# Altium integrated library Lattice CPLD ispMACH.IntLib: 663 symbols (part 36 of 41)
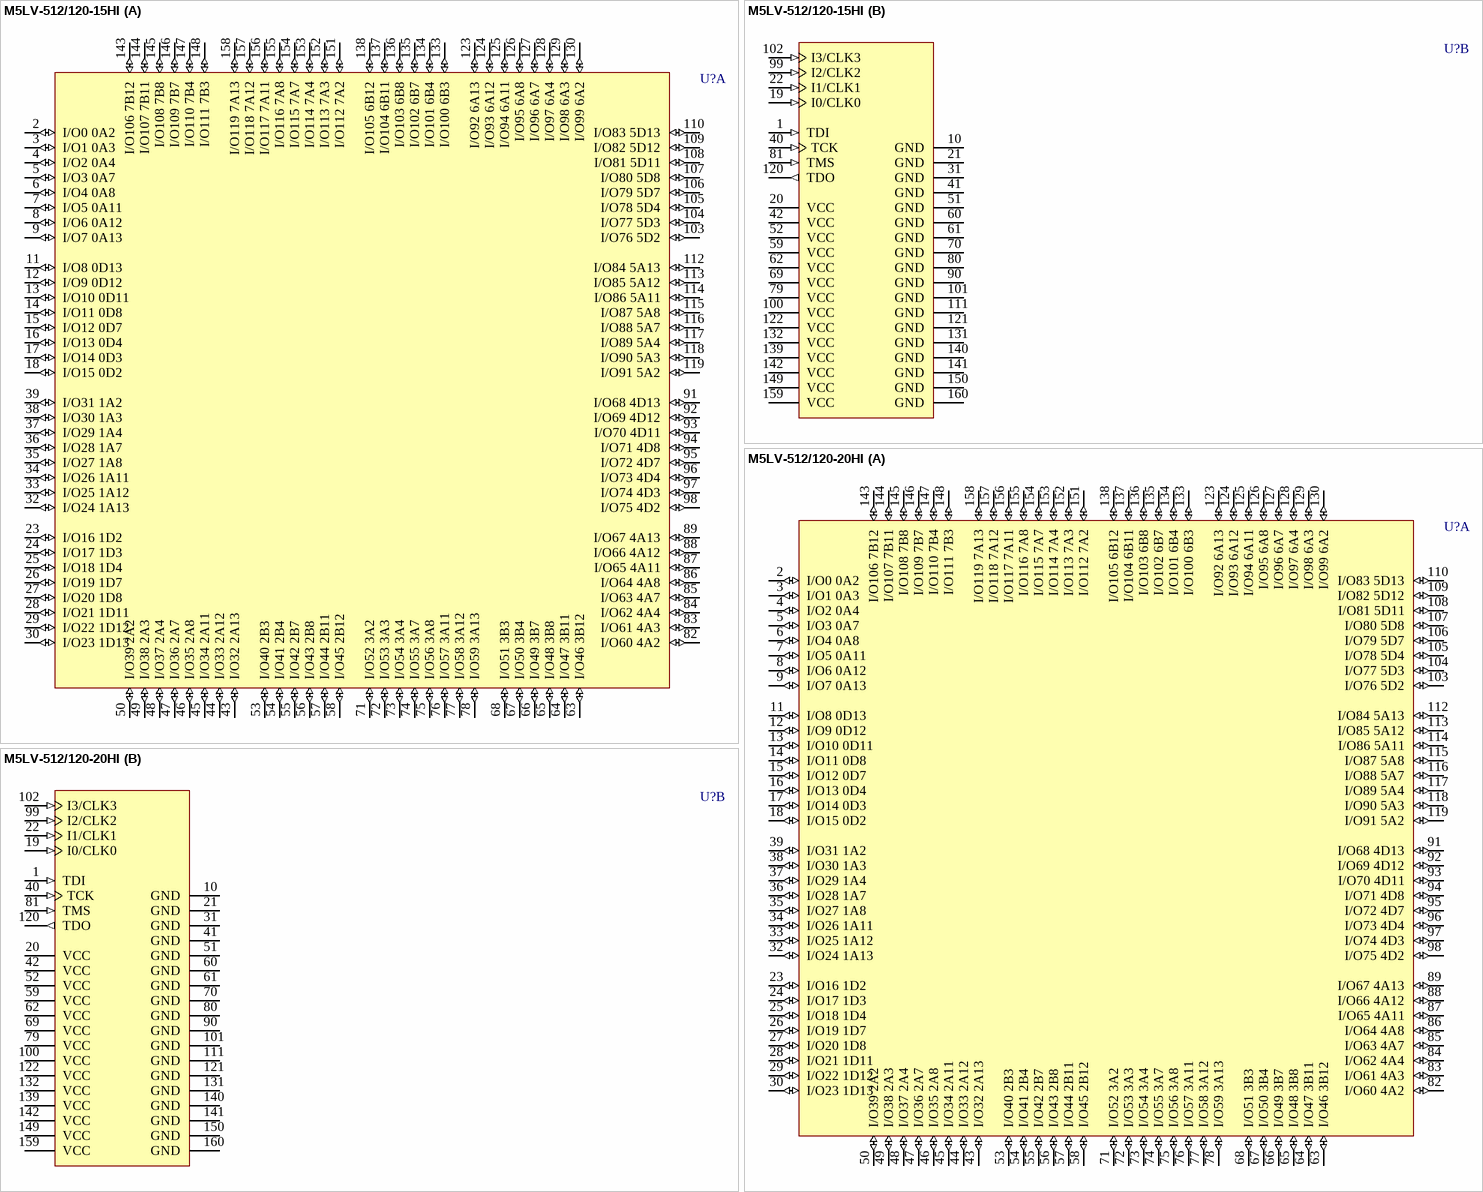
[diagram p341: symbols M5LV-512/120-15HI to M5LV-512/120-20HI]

## M5LV-512/120-15HI
designator U?
High-Density and High-I/O Complex PLD
footprint MQFP160_N (QFP, 160-Leads, Body 27.7 x 27.7mm, Pitch 0.65mm, IPC Medium Density)
footprint MQFP160_L (QFP, 160-Leads, Body 27.7 x 27.7mm, Pitch 0.65mm, IPC High Density)
footprint MQFP160_M (QFP, 160-Leads, Body 27.7 x 27.7mm, Pitch 0.65mm, IPC Low Density)
3D model M5LV-MQFP160 (160-Pin Quad Flat Pack 0.65 mm Pitch)
part A pins: 2 I/O0 0A2 (io), 3 I/O1 0A3 (io), 4 I/O2 0A4 (io), 5 I/O3 0A7 (io), 6 I/O4 0A8 (io), 7 I/O5 0A11 (io), 8 I/O6 0A12 (io), 9 I/O7 0A13 (io), 11 I/O8 0D13 (io), 12 I/O9 0D12 (io), 13 I/O10 0D11 (io), 14 I/O11 0D8 (io), 15 I/O12 0D7 (io), 16 I/O13 0D4 (io), 17 I/O14 0D3 (io), 18 I/O15 0D2 (io), 23 I/O16 1D2 (io), 24 I/O17 1D3 (io), 25 I/O18 1D4 (io), 26 I/O19 1D7 (io), 27 I/O20 1D8 (io), 28 I/O21 1D11 (io), 29 I/O22 1D12 (io), 30 I/O23 1D13 (io), 32 I/O24 1A13 (io), 33 I/O25 1A12 (io), 34 I/O26 1A11 (io), 35 I/O27 1A8 (io), 36 I/O28 1A7 (io), 37 I/O29 1A4 (io), 38 I/O30 1A3 (io), 39 I/O31 1A2 (io), 43 I/O32 2A13 (io), 44 I/O33 2A12 (io), 45 I/O34 2A11 (io), 46 I/O35 2A8 (io), 47 I/O36 2A7 (io), 48 I/O37 2A4 (io), 49 I/O38 2A3 (io), 50 I/O39 2A2 (io), 53 I/O40 2B3 (io), 54 I/O41 2B4 (io), 55 I/O42 2B7 (io), 56 I/O43 2B8 (io), 57 I/O44 2B11 (io), 58 I/O45 2B12 (io), 63 I/O46 3B12 (io), 64 I/O47 3B11 (io), 65 I/O48 3B8 (io), 66 I/O49 3B7 (io), 67 I/O50 3B4 (io), 68 I/O51 3B3 (io), 71 I/O52 3A2 (io), 72 I/O53 3A3 (io), 73 I/O54 3A4 (io), 74 I/O55 3A7 (io), 75 I/O56 3A8 (io), 76 I/O57 3A11 (io), 77 I/O58 3A12 (io), 78 I/O59 3A13 (io), 82 I/O60 4A2 (io), 83 I/O61 4A3 (io), 84 I/O62 4A4 (io), 85 I/O63 4A7 (io), 86 I/O64 4A8 (io), 87 I/O65 4A11 (io), 88 I/O66 4A12 (io), 89 I/O67 4A13 (io), 91 I/O68 4D13 (io), 92 I/O69 4D12 (io), 93 I/O70 4D11 (io), 94 I/O71 4D8 (io), 95 I/O72 4D7 (io), 96 I/O73 4D4 (io), 97 I/O74 4D3 (io), 98 I/O75 4D2 (io), 103 I/O76 5D2 (io), 104 I/O77 5D3 (io), 105 I/O78 5D4 (io), 106 I/O79 5D7 (io), 107 I/O80 5D8 (io), 108 I/O81 5D11 (io), 109 I/O82 5D12 (io), 110 I/O83 5D13 (io), 112 I/O84 5A13 (io), 113 I/O85 5A12 (io), 114 I/O86 5A11 (io), 115 I/O87 5A8 (io), 116 I/O88 5A7 (io), 117 I/O89 5A4 (io), 118 I/O90 5A3 (io), 119 I/O91 5A2 (io), 123 I/O92 6A13 (io), 124 I/O93 6A12 (io), 125 I/O94 6A11 (io), 126 I/O95 6A8 (io), 127 I/O96 6A7 (io), 128 I/O97 6A4 (io), 129 I/O98 6A3 (io), 130 I/O99 6A2 (io), 133 I/O100 6B3 (io), 134 I/O101 6B4 (io), 135 I/O102 6B7 (io), 136 I/O103 6B8 (io), 137 I/O104 6B11 (io), 138 I/O105 6B12 (io), 143 I/O106 7B12 (io), 144 I/O107 7B11 (io), 145 I/O108 7B8 (io), 146 I/O109 7B7 (io), 147 I/O110 7B4 (io), 148 I/O111 7B3 (io), 151 I/O112 7A2 (io), 152 I/O113 7A3 (io), 153 I/O114 7A4 (io), 154 I/O115 7A7 (io), 155 I/O116 7A8 (io), 156 I/O117 7A11 (io), 157 I/O118 7A12 (io), 158 I/O119 7A13 (io)
part B pins: 1 TDI (in), 10 GND (power), 19 I0/CLK0 (in), 20 VCC (power), 21 GND (power), 22 I1/CLK1 (in), 31 GND (power), 40 TCK (in), 41 GND (power), 42 VCC (power), 51 GND (power), 52 VCC (power), 59 VCC (power), 60 GND (power), 61 GND (power), 62 VCC (power), 69 VCC (power), 70 GND (power), 79 VCC (power), 80 GND (power), 81 TMS (in), 90 GND (power), 99 I2/CLK2 (in), 100 VCC (power), 101 GND (power), 102 I3/CLK3 (in), 111 GND (power), 120 TDO (out), 121 GND (power), 122 VCC (power), 131 GND (power), 132 VCC (power), 139 VCC (power), 140 GND (power), 141 GND (power), 142 VCC (power), 149 VCC (power), 150 GND (power), 159 VCC (power), 160 GND (power)

## M5LV-512/120-20HI
designator U?
High-Density and High-I/O Complex PLD
footprint MQFP160_N (QFP, 160-Leads, Body 27.7 x 27.7mm, Pitch 0.65mm, IPC Medium Density)
footprint MQFP160_L (QFP, 160-Leads, Body 27.7 x 27.7mm, Pitch 0.65mm, IPC High Density)
footprint MQFP160_M (QFP, 160-Leads, Body 27.7 x 27.7mm, Pitch 0.65mm, IPC Low Density)
3D model M5LV-MQFP160 (160-Pin Quad Flat Pack 0.65 mm Pitch)
part A pins: 2 I/O0 0A2 (io), 3 I/O1 0A3 (io), 4 I/O2 0A4 (io), 5 I/O3 0A7 (io), 6 I/O4 0A8 (io), 7 I/O5 0A11 (io), 8 I/O6 0A12 (io), 9 I/O7 0A13 (io), 11 I/O8 0D13 (io), 12 I/O9 0D12 (io), 13 I/O10 0D11 (io), 14 I/O11 0D8 (io), 15 I/O12 0D7 (io), 16 I/O13 0D4 (io), 17 I/O14 0D3 (io), 18 I/O15 0D2 (io), 23 I/O16 1D2 (io), 24 I/O17 1D3 (io), 25 I/O18 1D4 (io), 26 I/O19 1D7 (io), 27 I/O20 1D8 (io), 28 I/O21 1D11 (io), 29 I/O22 1D12 (io), 30 I/O23 1D13 (io), 32 I/O24 1A13 (io), 33 I/O25 1A12 (io), 34 I/O26 1A11 (io), 35 I/O27 1A8 (io), 36 I/O28 1A7 (io), 37 I/O29 1A4 (io), 38 I/O30 1A3 (io), 39 I/O31 1A2 (io), 43 I/O32 2A13 (io), 44 I/O33 2A12 (io), 45 I/O34 2A11 (io), 46 I/O35 2A8 (io), 47 I/O36 2A7 (io), 48 I/O37 2A4 (io), 49 I/O38 2A3 (io), 50 I/O39 2A2 (io), 53 I/O40 2B3 (io), 54 I/O41 2B4 (io), 55 I/O42 2B7 (io), 56 I/O43 2B8 (io), 57 I/O44 2B11 (io), 58 I/O45 2B12 (io), 63 I/O46 3B12 (io), 64 I/O47 3B11 (io), 65 I/O48 3B8 (io), 66 I/O49 3B7 (io), 67 I/O50 3B4 (io), 68 I/O51 3B3 (io), 71 I/O52 3A2 (io), 72 I/O53 3A3 (io), 73 I/O54 3A4 (io), 74 I/O55 3A7 (io), 75 I/O56 3A8 (io), 76 I/O57 3A11 (io), 77 I/O58 3A12 (io), 78 I/O59 3A13 (io), 82 I/O60 4A2 (io), 83 I/O61 4A3 (io), 84 I/O62 4A4 (io), 85 I/O63 4A7 (io), 86 I/O64 4A8 (io), 87 I/O65 4A11 (io), 88 I/O66 4A12 (io), 89 I/O67 4A13 (io), 91 I/O68 4D13 (io), 92 I/O69 4D12 (io), 93 I/O70 4D11 (io), 94 I/O71 4D8 (io), 95 I/O72 4D7 (io), 96 I/O73 4D4 (io), 97 I/O74 4D3 (io), 98 I/O75 4D2 (io), 103 I/O76 5D2 (io), 104 I/O77 5D3 (io), 105 I/O78 5D4 (io), 106 I/O79 5D7 (io), 107 I/O80 5D8 (io), 108 I/O81 5D11 (io), 109 I/O82 5D12 (io), 110 I/O83 5D13 (io), 112 I/O84 5A13 (io), 113 I/O85 5A12 (io), 114 I/O86 5A11 (io), 115 I/O87 5A8 (io), 116 I/O88 5A7 (io), 117 I/O89 5A4 (io), 118 I/O90 5A3 (io), 119 I/O91 5A2 (io), 123 I/O92 6A13 (io), 124 I/O93 6A12 (io), 125 I/O94 6A11 (io), 126 I/O95 6A8 (io), 127 I/O96 6A7 (io), 128 I/O97 6A4 (io), 129 I/O98 6A3 (io), 130 I/O99 6A2 (io), 133 I/O100 6B3 (io), 134 I/O101 6B4 (io), 135 I/O102 6B7 (io), 136 I/O103 6B8 (io), 137 I/O104 6B11 (io), 138 I/O105 6B12 (io), 143 I/O106 7B12 (io), 144 I/O107 7B11 (io), 145 I/O108 7B8 (io), 146 I/O109 7B7 (io), 147 I/O110 7B4 (io), 148 I/O111 7B3 (io), 151 I/O112 7A2 (io), 152 I/O113 7A3 (io), 153 I/O114 7A4 (io), 154 I/O115 7A7 (io), 155 I/O116 7A8 (io), 156 I/O117 7A11 (io), 157 I/O118 7A12 (io), 158 I/O119 7A13 (io)
part B pins: 1 TDI (in), 10 GND (power), 19 I0/CLK0 (in), 20 VCC (power), 21 GND (power), 22 I1/CLK1 (in), 31 GND (power), 40 TCK (in), 41 GND (power), 42 VCC (power), 51 GND (power), 52 VCC (power), 59 VCC (power), 60 GND (power), 61 GND (power), 62 VCC (power), 69 VCC (power), 70 GND (power), 79 VCC (power), 80 GND (power), 81 TMS (in), 90 GND (power), 99 I2/CLK2 (in), 100 VCC (power), 101 GND (power), 102 I3/CLK3 (in), 111 GND (power), 120 TDO (out), 121 GND (power), 122 VCC (power), 131 GND (power), 132 VCC (power), 139 VCC (power), 140 GND (power), 141 GND (power), 142 VCC (power), 149 VCC (power), 150 GND (power), 159 VCC (power), 160 GND (power)

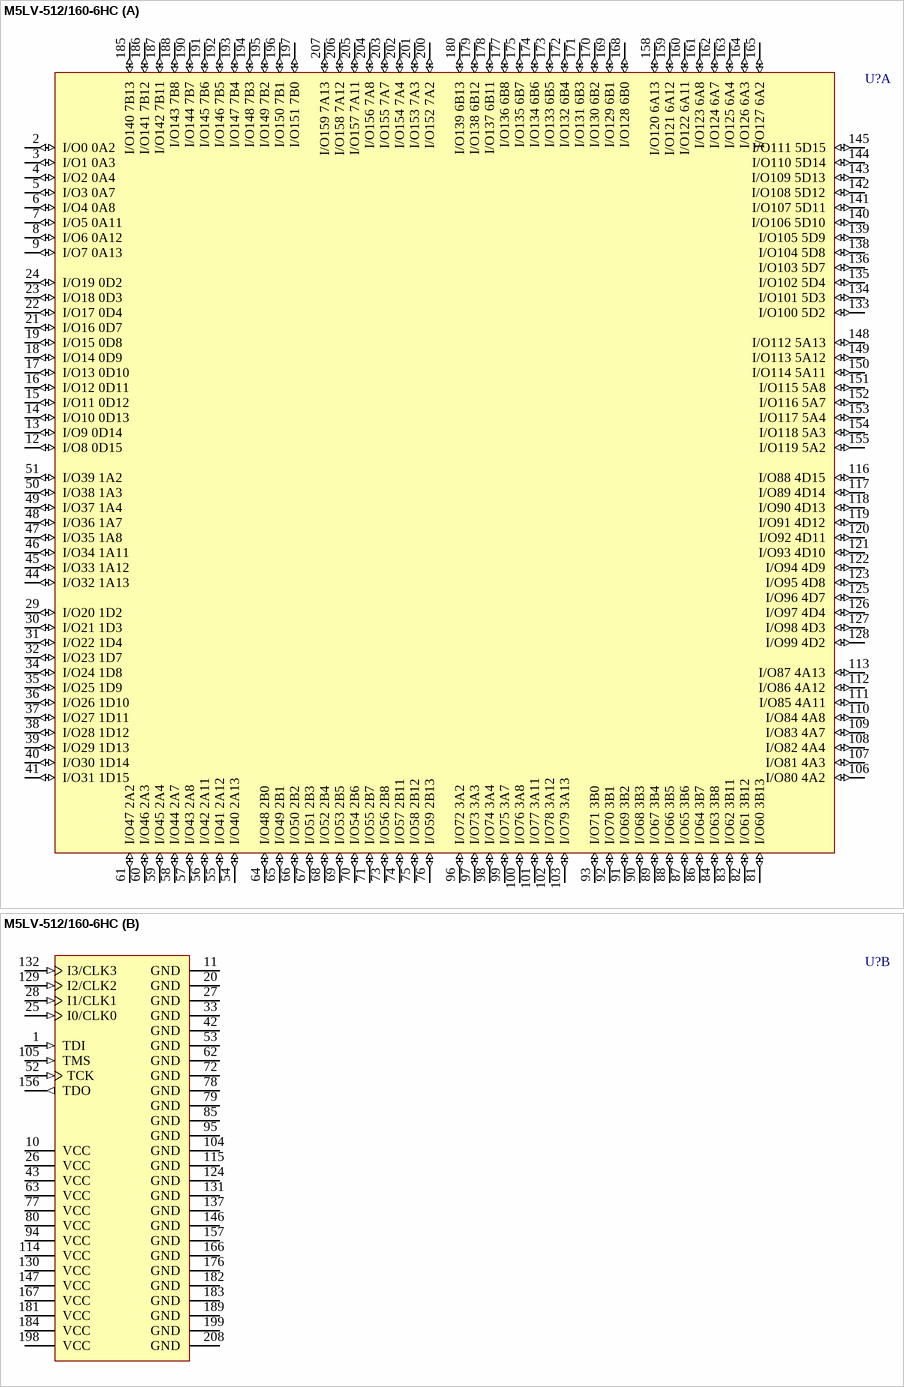
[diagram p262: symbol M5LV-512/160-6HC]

## M5LV-512/160-6HC
designator U?
High-Density and High-I/O Complex PLD
footprint MQFP208_N (Shrink QFP, 208-Leads, Body 27.7x27.7mm, Pitch 0.5mm, IPC Medium Density)
footprint MQFP208_L (Shrink QFP, 208-Leads, Body 27.7x27.7mm, Pitch 0.5mm, IPC High Density)
footprint MQFP208_M (Shrink QFP, 208-Leads, Body 27.7x27.7mm, Pitch 0.5mm, IPC Low Density)
3D model M5LV-MQFP208 (208-Pin Shrink Quad Flat Pack 0.5 mm Pitch)
part A pins: 2 I/O0 0A2 (io), 3 I/O1 0A3 (io), 4 I/O2 0A4 (io), 5 I/O3 0A7 (io), 6 I/O4 0A8 (io), 7 I/O5 0A11 (io), 8 I/O6 0A12 (io), 9 I/O7 0A13 (io), 12 I/O8 0D15 (io), 13 I/O9 0D14 (io), 14 I/O10 0D13 (io), 15 I/O11 0D12 (io), 16 I/O12 0D11 (io), 17 I/O13 0D10 (io), 18 I/O14 0D9 (io), 19 I/O15 0D8 (io), 21 I/O16 0D7 (io), 22 I/O17 0D4 (io), 23 I/O18 0D3 (io), 24 I/O19 0D2 (io), 29 I/O20 1D2 (io), 30 I/O21 1D3 (io), 31 I/O22 1D4 (io), 32 I/O23 1D7 (io), 34 I/O24 1D8 (io), 35 I/O25 1D9 (io), 36 I/O26 1D10 (io), 37 I/O27 1D11 (io), 38 I/O28 1D12 (io), 39 I/O29 1D13 (io), 40 I/O30 1D14 (io), 41 I/O31 1D15 (io), 44 I/O32 1A13 (io), 45 I/O33 1A12 (io), 46 I/O34 1A11 (io), 47 I/O35 1A8 (io), 48 I/O36 1A7 (io), 49 I/O37 1A4 (io), 50 I/O38 1A3 (io), 51 I/O39 1A2 (io), 54 I/O40 2A13 (io), 55 I/O41 2A12 (io), 56 I/O42 2A11 (io), 57 I/O43 2A8 (io), 58 I/O44 2A7 (io), 59 I/O45 2A4 (io), 60 I/O46 2A3 (io), 61 I/O47 2A2 (io), 64 I/O48 2B0 (io), 65 I/O49 2B1 (io), 66 I/O50 2B2 (io), 67 I/O51 2B3 (io), 68 I/O52 2B4 (io), 69 I/O53 2B5 (io), 70 I/O54 2B6 (io), 71 I/O55 2B7 (io), 73 I/O56 2B8 (io), 74 I/O57 2B11 (io), 75 I/O58 2B12 (io), 76 I/O59 2B13 (io), 81 I/O60 3B13 (io), 82 I/O61 3B12 (io), 83 I/O62 3B11 (io), 84 I/O63 3B8 (io), 86 I/O64 3B7 (io), 87 I/O65 3B6 (io), 88 I/O66 3B5 (io), 89 I/O67 3B4 (io), 90 I/O68 3B3 (io), 91 I/O69 3B2 (io), 92 I/O70 3B1 (io), 93 I/O71 3B0 (io), 96 I/O72 3A2 (io), 97 I/O73 3A3 (io), 98 I/O74 3A4 (io), 99 I/O75 3A7 (io), 100 I/O76 3A8 (io), 101 I/O77 3A11 (io), 102 I/O78 3A12 (io), 103 I/O79 3A13 (io), 106 I/O80 4A2 (io), 107 I/O81 4A3 (io), 108 I/O82 4A4 (io), 109 I/O83 4A7 (io), 110 I/O84 4A8 (io), 111 I/O85 4A11 (io), 112 I/O86 4A12 (io), 113 I/O87 4A13 (io), 116 I/O88 4D15 (io), 117 I/O89 4D14 (io), 118 I/O90 4D13 (io), 119 I/O91 4D12 (io), 120 I/O92 4D11 (io), 121 I/O93 4D10 (io), 122 I/O94 4D9 (io), 123 I/O95 4D8 (io), 125 I/O96 4D7 (io), 126 I/O97 4D4 (io), 127 I/O98 4D3 (io), 128 I/O99 4D2 (io), 133 I/O100 5D2 (io), 134 I/O101 5D3 (io), 135 I/O102 5D4 (io), 136 I/O103 5D7 (io), 138 I/O104 5D8 (io), 139 I/O105 5D9 (io), 140 I/O106 5D10 (io), 141 I/O107 5D11 (io), 142 I/O108 5D12 (io), 143 I/O109 5D13 (io), 144 I/O110 5D14 (io), 145 I/O111 5D15 (io), 148 I/O112 5A13 (io), 149 I/O113 5A12 (io), 150 I/O114 5A11 (io), 151 I/O115 5A8 (io), 152 I/O116 5A7 (io), 153 I/O117 5A4 (io), 154 I/O118 5A3 (io), 155 I/O119 5A2 (io), 158 I/O120 6A13 (io), 159 I/O121 6A12 (io), 160 I/O122 6A11 (io), 161 I/O123 6A8 (io), 162 I/O124 6A7 (io), 163 I/O125 6A4 (io), 164 I/O126 6A3 (io), 165 I/O127 6A2 (io), 168 I/O128 6B0 (io), 169 I/O129 6B1 (io), 170 I/O130 6B2 (io), 171 I/O131 6B3 (io), 172 I/O132 6B4 (io), 173 I/O133 6B5 (io), 174 I/O134 6B6 (io), 175 I/O135 6B7 (io), 177 I/O136 6B8 (io), 178 I/O137 6B11 (io), 179 I/O138 6B12 (io), 180 I/O139 6B13 (io), 185 I/O140 7B13 (io), 186 I/O141 7B12 (io), 187 I/O142 7B11 (io), 188 I/O143 7B8 (io), 190 I/O144 7B7 (io), 191 I/O145 7B6 (io), 192 I/O146 7B5 (io), 193 I/O147 7B4 (io), 194 I/O148 7B3 (io), 195 I/O149 7B2 (io), 196 I/O150 7B1 (io), 197 I/O151 7B0 (io), 200 I/O152 7A2 (io), 201 I/O153 7A3 (io), 202 I/O154 7A4 (io), 203 I/O155 7A7 (io), 204 I/O156 7A8 (io), 205 I/O157 7A11 (io), 206 I/O158 7A12 (io), 207 I/O159 7A13 (io)
part B pins: 1 TDI (in), 10 VCC (power), 11 GND (power), 20 GND (power), 25 I0/CLK0 (in), 26 VCC (power), 27 GND (power), 28 I1/CLK1 (in), 33 GND (power), 42 GND (power), 43 VCC (power), 52 TCK (in), 53 GND (power), 62 GND (power), 63 VCC (power), 72 GND (power), 77 VCC (power), 78 GND (power), 79 GND (power), 80 VCC (power), 85 GND (power), 94 VCC (power), 95 GND (power), 104 GND (power), 105 TMS (in), 114 VCC (power), 115 GND (power), 124 GND (power), 129 I2/CLK2 (in), 130 VCC (power), 131 GND (power), 132 I3/CLK3 (in), 137 GND (power), 146 GND (power), 147 VCC (power), 156 TDO (out), 157 GND (power), 166 GND (power), 167 VCC (power), 176 GND (power), 181 VCC (power), 182 GND (power), 183 GND (power), 184 VCC (power), 189 GND (power), 198 VCC (power), 199 GND (power), 208 GND (power)

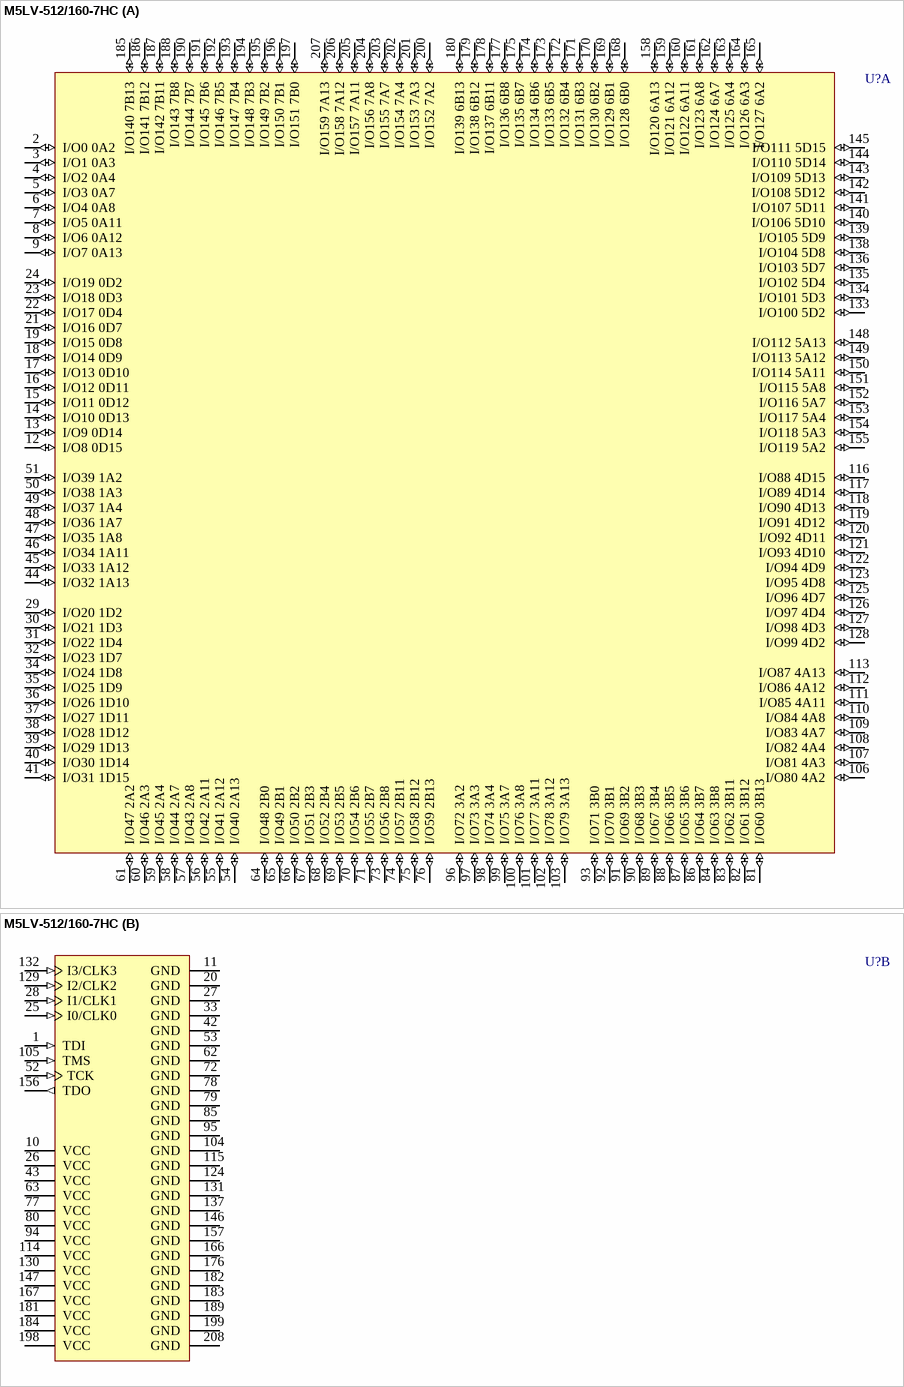
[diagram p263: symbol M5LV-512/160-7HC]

## M5LV-512/160-7HC
designator U?
High-Density and High-I/O Complex PLD
footprint MQFP208_N (Shrink QFP, 208-Leads, Body 27.7x27.7mm, Pitch 0.5mm, IPC Medium Density)
footprint MQFP208_L (Shrink QFP, 208-Leads, Body 27.7x27.7mm, Pitch 0.5mm, IPC High Density)
footprint MQFP208_M (Shrink QFP, 208-Leads, Body 27.7x27.7mm, Pitch 0.5mm, IPC Low Density)
3D model M5LV-MQFP208 (208-Pin Shrink Quad Flat Pack 0.5 mm Pitch)
part A pins: 2 I/O0 0A2 (io), 3 I/O1 0A3 (io), 4 I/O2 0A4 (io), 5 I/O3 0A7 (io), 6 I/O4 0A8 (io), 7 I/O5 0A11 (io), 8 I/O6 0A12 (io), 9 I/O7 0A13 (io), 12 I/O8 0D15 (io), 13 I/O9 0D14 (io), 14 I/O10 0D13 (io), 15 I/O11 0D12 (io), 16 I/O12 0D11 (io), 17 I/O13 0D10 (io), 18 I/O14 0D9 (io), 19 I/O15 0D8 (io), 21 I/O16 0D7 (io), 22 I/O17 0D4 (io), 23 I/O18 0D3 (io), 24 I/O19 0D2 (io), 29 I/O20 1D2 (io), 30 I/O21 1D3 (io), 31 I/O22 1D4 (io), 32 I/O23 1D7 (io), 34 I/O24 1D8 (io), 35 I/O25 1D9 (io), 36 I/O26 1D10 (io), 37 I/O27 1D11 (io), 38 I/O28 1D12 (io), 39 I/O29 1D13 (io), 40 I/O30 1D14 (io), 41 I/O31 1D15 (io), 44 I/O32 1A13 (io), 45 I/O33 1A12 (io), 46 I/O34 1A11 (io), 47 I/O35 1A8 (io), 48 I/O36 1A7 (io), 49 I/O37 1A4 (io), 50 I/O38 1A3 (io), 51 I/O39 1A2 (io), 54 I/O40 2A13 (io), 55 I/O41 2A12 (io), 56 I/O42 2A11 (io), 57 I/O43 2A8 (io), 58 I/O44 2A7 (io), 59 I/O45 2A4 (io), 60 I/O46 2A3 (io), 61 I/O47 2A2 (io), 64 I/O48 2B0 (io), 65 I/O49 2B1 (io), 66 I/O50 2B2 (io), 67 I/O51 2B3 (io), 68 I/O52 2B4 (io), 69 I/O53 2B5 (io), 70 I/O54 2B6 (io), 71 I/O55 2B7 (io), 73 I/O56 2B8 (io), 74 I/O57 2B11 (io), 75 I/O58 2B12 (io), 76 I/O59 2B13 (io), 81 I/O60 3B13 (io), 82 I/O61 3B12 (io), 83 I/O62 3B11 (io), 84 I/O63 3B8 (io), 86 I/O64 3B7 (io), 87 I/O65 3B6 (io), 88 I/O66 3B5 (io), 89 I/O67 3B4 (io), 90 I/O68 3B3 (io), 91 I/O69 3B2 (io), 92 I/O70 3B1 (io), 93 I/O71 3B0 (io), 96 I/O72 3A2 (io), 97 I/O73 3A3 (io), 98 I/O74 3A4 (io), 99 I/O75 3A7 (io), 100 I/O76 3A8 (io), 101 I/O77 3A11 (io), 102 I/O78 3A12 (io), 103 I/O79 3A13 (io), 106 I/O80 4A2 (io), 107 I/O81 4A3 (io), 108 I/O82 4A4 (io), 109 I/O83 4A7 (io), 110 I/O84 4A8 (io), 111 I/O85 4A11 (io), 112 I/O86 4A12 (io), 113 I/O87 4A13 (io), 116 I/O88 4D15 (io), 117 I/O89 4D14 (io), 118 I/O90 4D13 (io), 119 I/O91 4D12 (io), 120 I/O92 4D11 (io), 121 I/O93 4D10 (io), 122 I/O94 4D9 (io), 123 I/O95 4D8 (io), 125 I/O96 4D7 (io), 126 I/O97 4D4 (io), 127 I/O98 4D3 (io), 128 I/O99 4D2 (io), 133 I/O100 5D2 (io), 134 I/O101 5D3 (io), 135 I/O102 5D4 (io), 136 I/O103 5D7 (io), 138 I/O104 5D8 (io), 139 I/O105 5D9 (io), 140 I/O106 5D10 (io), 141 I/O107 5D11 (io), 142 I/O108 5D12 (io), 143 I/O109 5D13 (io), 144 I/O110 5D14 (io), 145 I/O111 5D15 (io), 148 I/O112 5A13 (io), 149 I/O113 5A12 (io), 150 I/O114 5A11 (io), 151 I/O115 5A8 (io), 152 I/O116 5A7 (io), 153 I/O117 5A4 (io), 154 I/O118 5A3 (io), 155 I/O119 5A2 (io), 158 I/O120 6A13 (io), 159 I/O121 6A12 (io), 160 I/O122 6A11 (io), 161 I/O123 6A8 (io), 162 I/O124 6A7 (io), 163 I/O125 6A4 (io), 164 I/O126 6A3 (io), 165 I/O127 6A2 (io), 168 I/O128 6B0 (io), 169 I/O129 6B1 (io), 170 I/O130 6B2 (io), 171 I/O131 6B3 (io), 172 I/O132 6B4 (io), 173 I/O133 6B5 (io), 174 I/O134 6B6 (io), 175 I/O135 6B7 (io), 177 I/O136 6B8 (io), 178 I/O137 6B11 (io), 179 I/O138 6B12 (io), 180 I/O139 6B13 (io), 185 I/O140 7B13 (io), 186 I/O141 7B12 (io), 187 I/O142 7B11 (io), 188 I/O143 7B8 (io), 190 I/O144 7B7 (io), 191 I/O145 7B6 (io), 192 I/O146 7B5 (io), 193 I/O147 7B4 (io), 194 I/O148 7B3 (io), 195 I/O149 7B2 (io), 196 I/O150 7B1 (io), 197 I/O151 7B0 (io), 200 I/O152 7A2 (io), 201 I/O153 7A3 (io), 202 I/O154 7A4 (io), 203 I/O155 7A7 (io), 204 I/O156 7A8 (io), 205 I/O157 7A11 (io), 206 I/O158 7A12 (io), 207 I/O159 7A13 (io)
part B pins: 1 TDI (in), 10 VCC (power), 11 GND (power), 20 GND (power), 25 I0/CLK0 (in), 26 VCC (power), 27 GND (power), 28 I1/CLK1 (in), 33 GND (power), 42 GND (power), 43 VCC (power), 52 TCK (in), 53 GND (power), 62 GND (power), 63 VCC (power), 72 GND (power), 77 VCC (power), 78 GND (power), 79 GND (power), 80 VCC (power), 85 GND (power), 94 VCC (power), 95 GND (power), 104 GND (power), 105 TMS (in), 114 VCC (power), 115 GND (power), 124 GND (power), 129 I2/CLK2 (in), 130 VCC (power), 131 GND (power), 132 I3/CLK3 (in), 137 GND (power), 146 GND (power), 147 VCC (power), 156 TDO (out), 157 GND (power), 166 GND (power), 167 VCC (power), 176 GND (power), 181 VCC (power), 182 GND (power), 183 GND (power), 184 VCC (power), 189 GND (power), 198 VCC (power), 199 GND (power), 208 GND (power)

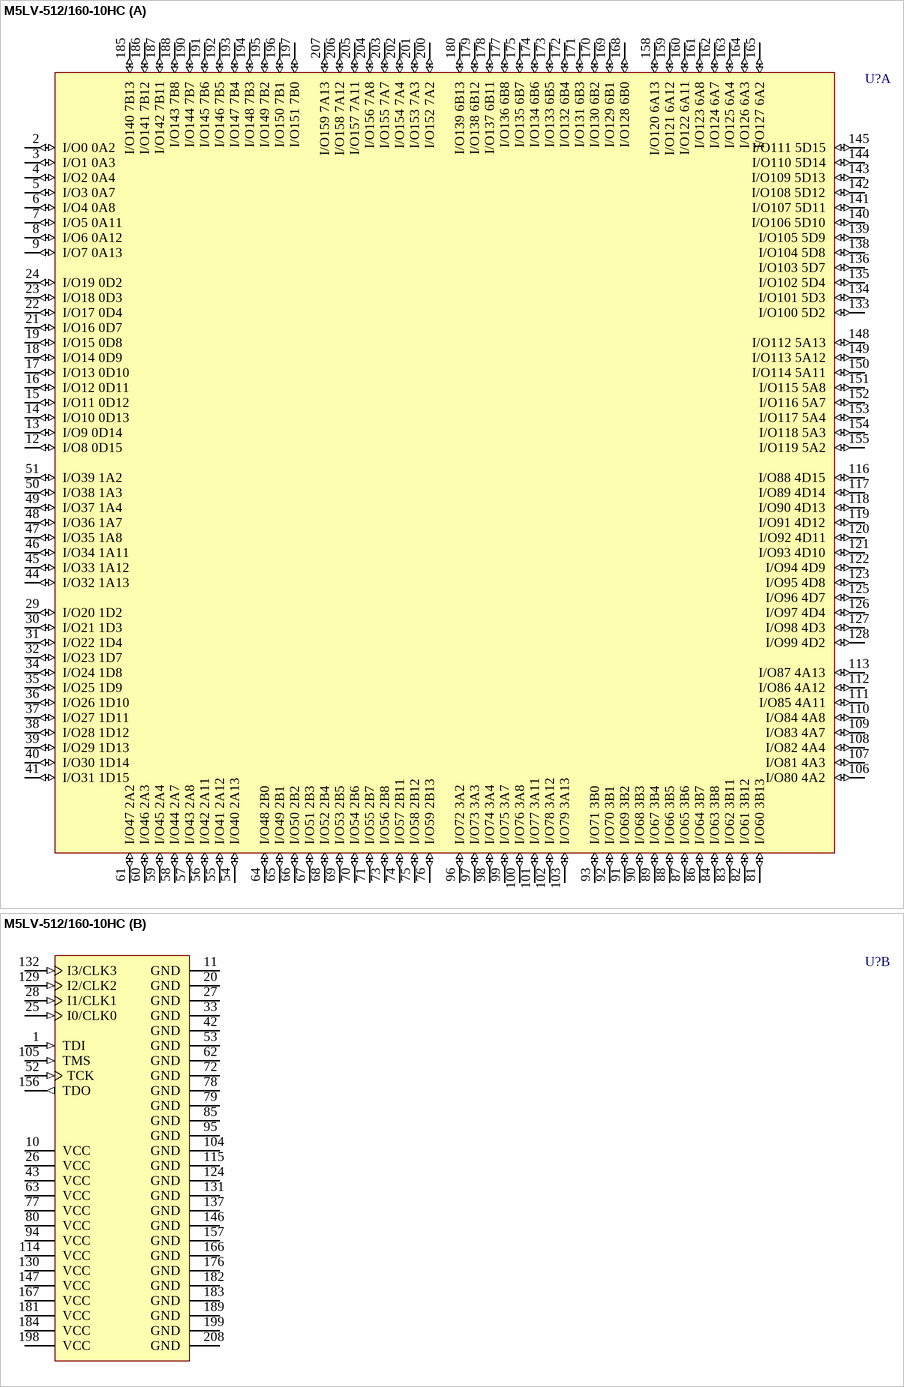
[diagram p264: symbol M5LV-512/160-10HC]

## M5LV-512/160-10HC
designator U?
High-Density and High-I/O Complex PLD
footprint MQFP208_N (Shrink QFP, 208-Leads, Body 27.7x27.7mm, Pitch 0.5mm, IPC Medium Density)
footprint MQFP208_L (Shrink QFP, 208-Leads, Body 27.7x27.7mm, Pitch 0.5mm, IPC High Density)
footprint MQFP208_M (Shrink QFP, 208-Leads, Body 27.7x27.7mm, Pitch 0.5mm, IPC Low Density)
3D model M5LV-MQFP208 (208-Pin Shrink Quad Flat Pack 0.5 mm Pitch)
part A pins: 2 I/O0 0A2 (io), 3 I/O1 0A3 (io), 4 I/O2 0A4 (io), 5 I/O3 0A7 (io), 6 I/O4 0A8 (io), 7 I/O5 0A11 (io), 8 I/O6 0A12 (io), 9 I/O7 0A13 (io), 12 I/O8 0D15 (io), 13 I/O9 0D14 (io), 14 I/O10 0D13 (io), 15 I/O11 0D12 (io), 16 I/O12 0D11 (io), 17 I/O13 0D10 (io), 18 I/O14 0D9 (io), 19 I/O15 0D8 (io), 21 I/O16 0D7 (io), 22 I/O17 0D4 (io), 23 I/O18 0D3 (io), 24 I/O19 0D2 (io), 29 I/O20 1D2 (io), 30 I/O21 1D3 (io), 31 I/O22 1D4 (io), 32 I/O23 1D7 (io), 34 I/O24 1D8 (io), 35 I/O25 1D9 (io), 36 I/O26 1D10 (io), 37 I/O27 1D11 (io), 38 I/O28 1D12 (io), 39 I/O29 1D13 (io), 40 I/O30 1D14 (io), 41 I/O31 1D15 (io), 44 I/O32 1A13 (io), 45 I/O33 1A12 (io), 46 I/O34 1A11 (io), 47 I/O35 1A8 (io), 48 I/O36 1A7 (io), 49 I/O37 1A4 (io), 50 I/O38 1A3 (io), 51 I/O39 1A2 (io), 54 I/O40 2A13 (io), 55 I/O41 2A12 (io), 56 I/O42 2A11 (io), 57 I/O43 2A8 (io), 58 I/O44 2A7 (io), 59 I/O45 2A4 (io), 60 I/O46 2A3 (io), 61 I/O47 2A2 (io), 64 I/O48 2B0 (io), 65 I/O49 2B1 (io), 66 I/O50 2B2 (io), 67 I/O51 2B3 (io), 68 I/O52 2B4 (io), 69 I/O53 2B5 (io), 70 I/O54 2B6 (io), 71 I/O55 2B7 (io), 73 I/O56 2B8 (io), 74 I/O57 2B11 (io), 75 I/O58 2B12 (io), 76 I/O59 2B13 (io), 81 I/O60 3B13 (io), 82 I/O61 3B12 (io), 83 I/O62 3B11 (io), 84 I/O63 3B8 (io), 86 I/O64 3B7 (io), 87 I/O65 3B6 (io), 88 I/O66 3B5 (io), 89 I/O67 3B4 (io), 90 I/O68 3B3 (io), 91 I/O69 3B2 (io), 92 I/O70 3B1 (io), 93 I/O71 3B0 (io), 96 I/O72 3A2 (io), 97 I/O73 3A3 (io), 98 I/O74 3A4 (io), 99 I/O75 3A7 (io), 100 I/O76 3A8 (io), 101 I/O77 3A11 (io), 102 I/O78 3A12 (io), 103 I/O79 3A13 (io), 106 I/O80 4A2 (io), 107 I/O81 4A3 (io), 108 I/O82 4A4 (io), 109 I/O83 4A7 (io), 110 I/O84 4A8 (io), 111 I/O85 4A11 (io), 112 I/O86 4A12 (io), 113 I/O87 4A13 (io), 116 I/O88 4D15 (io), 117 I/O89 4D14 (io), 118 I/O90 4D13 (io), 119 I/O91 4D12 (io), 120 I/O92 4D11 (io), 121 I/O93 4D10 (io), 122 I/O94 4D9 (io), 123 I/O95 4D8 (io), 125 I/O96 4D7 (io), 126 I/O97 4D4 (io), 127 I/O98 4D3 (io), 128 I/O99 4D2 (io), 133 I/O100 5D2 (io), 134 I/O101 5D3 (io), 135 I/O102 5D4 (io), 136 I/O103 5D7 (io), 138 I/O104 5D8 (io), 139 I/O105 5D9 (io), 140 I/O106 5D10 (io), 141 I/O107 5D11 (io), 142 I/O108 5D12 (io), 143 I/O109 5D13 (io), 144 I/O110 5D14 (io), 145 I/O111 5D15 (io), 148 I/O112 5A13 (io), 149 I/O113 5A12 (io), 150 I/O114 5A11 (io), 151 I/O115 5A8 (io), 152 I/O116 5A7 (io), 153 I/O117 5A4 (io), 154 I/O118 5A3 (io), 155 I/O119 5A2 (io), 158 I/O120 6A13 (io), 159 I/O121 6A12 (io), 160 I/O122 6A11 (io), 161 I/O123 6A8 (io), 162 I/O124 6A7 (io), 163 I/O125 6A4 (io), 164 I/O126 6A3 (io), 165 I/O127 6A2 (io), 168 I/O128 6B0 (io), 169 I/O129 6B1 (io), 170 I/O130 6B2 (io), 171 I/O131 6B3 (io), 172 I/O132 6B4 (io), 173 I/O133 6B5 (io), 174 I/O134 6B6 (io), 175 I/O135 6B7 (io), 177 I/O136 6B8 (io), 178 I/O137 6B11 (io), 179 I/O138 6B12 (io), 180 I/O139 6B13 (io), 185 I/O140 7B13 (io), 186 I/O141 7B12 (io), 187 I/O142 7B11 (io), 188 I/O143 7B8 (io), 190 I/O144 7B7 (io), 191 I/O145 7B6 (io), 192 I/O146 7B5 (io), 193 I/O147 7B4 (io), 194 I/O148 7B3 (io), 195 I/O149 7B2 (io), 196 I/O150 7B1 (io), 197 I/O151 7B0 (io), 200 I/O152 7A2 (io), 201 I/O153 7A3 (io), 202 I/O154 7A4 (io), 203 I/O155 7A7 (io), 204 I/O156 7A8 (io), 205 I/O157 7A11 (io), 206 I/O158 7A12 (io), 207 I/O159 7A13 (io)
part B pins: 1 TDI (in), 10 VCC (power), 11 GND (power), 20 GND (power), 25 I0/CLK0 (in), 26 VCC (power), 27 GND (power), 28 I1/CLK1 (in), 33 GND (power), 42 GND (power), 43 VCC (power), 52 TCK (in), 53 GND (power), 62 GND (power), 63 VCC (power), 72 GND (power), 77 VCC (power), 78 GND (power), 79 GND (power), 80 VCC (power), 85 GND (power), 94 VCC (power), 95 GND (power), 104 GND (power), 105 TMS (in), 114 VCC (power), 115 GND (power), 124 GND (power), 129 I2/CLK2 (in), 130 VCC (power), 131 GND (power), 132 I3/CLK3 (in), 137 GND (power), 146 GND (power), 147 VCC (power), 156 TDO (out), 157 GND (power), 166 GND (power), 167 VCC (power), 176 GND (power), 181 VCC (power), 182 GND (power), 183 GND (power), 184 VCC (power), 189 GND (power), 198 VCC (power), 199 GND (power), 208 GND (power)

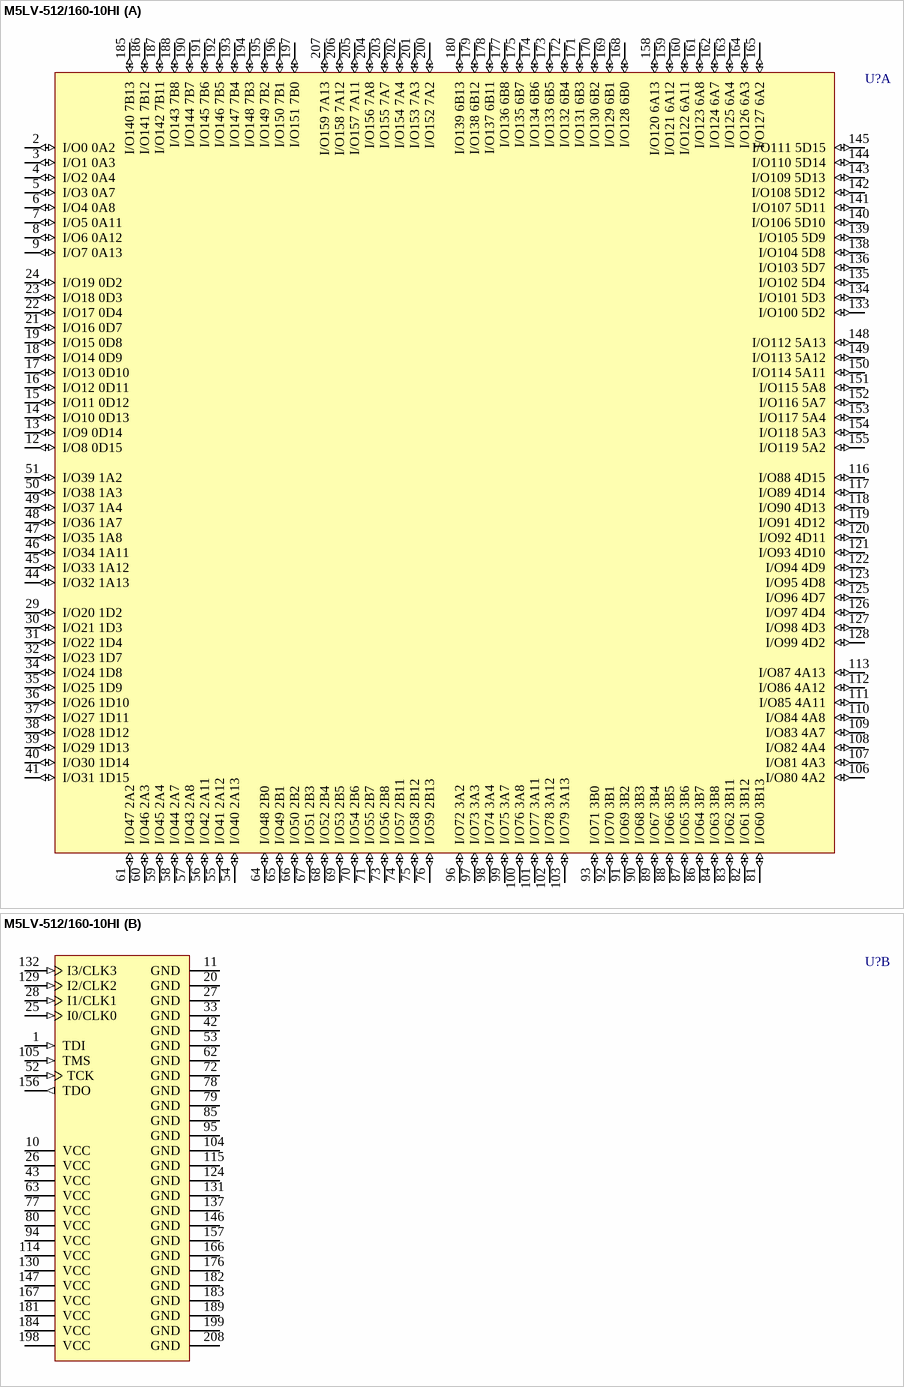
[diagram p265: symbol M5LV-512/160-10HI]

## M5LV-512/160-10HI
designator U?
High-Density and High-I/O Complex PLD
footprint MQFP208_N (Shrink QFP, 208-Leads, Body 27.7x27.7mm, Pitch 0.5mm, IPC Medium Density)
footprint MQFP208_L (Shrink QFP, 208-Leads, Body 27.7x27.7mm, Pitch 0.5mm, IPC High Density)
footprint MQFP208_M (Shrink QFP, 208-Leads, Body 27.7x27.7mm, Pitch 0.5mm, IPC Low Density)
3D model M5LV-MQFP208 (208-Pin Shrink Quad Flat Pack 0.5 mm Pitch)
part A pins: 2 I/O0 0A2 (io), 3 I/O1 0A3 (io), 4 I/O2 0A4 (io), 5 I/O3 0A7 (io), 6 I/O4 0A8 (io), 7 I/O5 0A11 (io), 8 I/O6 0A12 (io), 9 I/O7 0A13 (io), 12 I/O8 0D15 (io), 13 I/O9 0D14 (io), 14 I/O10 0D13 (io), 15 I/O11 0D12 (io), 16 I/O12 0D11 (io), 17 I/O13 0D10 (io), 18 I/O14 0D9 (io), 19 I/O15 0D8 (io), 21 I/O16 0D7 (io), 22 I/O17 0D4 (io), 23 I/O18 0D3 (io), 24 I/O19 0D2 (io), 29 I/O20 1D2 (io), 30 I/O21 1D3 (io), 31 I/O22 1D4 (io), 32 I/O23 1D7 (io), 34 I/O24 1D8 (io), 35 I/O25 1D9 (io), 36 I/O26 1D10 (io), 37 I/O27 1D11 (io), 38 I/O28 1D12 (io), 39 I/O29 1D13 (io), 40 I/O30 1D14 (io), 41 I/O31 1D15 (io), 44 I/O32 1A13 (io), 45 I/O33 1A12 (io), 46 I/O34 1A11 (io), 47 I/O35 1A8 (io), 48 I/O36 1A7 (io), 49 I/O37 1A4 (io), 50 I/O38 1A3 (io), 51 I/O39 1A2 (io), 54 I/O40 2A13 (io), 55 I/O41 2A12 (io), 56 I/O42 2A11 (io), 57 I/O43 2A8 (io), 58 I/O44 2A7 (io), 59 I/O45 2A4 (io), 60 I/O46 2A3 (io), 61 I/O47 2A2 (io), 64 I/O48 2B0 (io), 65 I/O49 2B1 (io), 66 I/O50 2B2 (io), 67 I/O51 2B3 (io), 68 I/O52 2B4 (io), 69 I/O53 2B5 (io), 70 I/O54 2B6 (io), 71 I/O55 2B7 (io), 73 I/O56 2B8 (io), 74 I/O57 2B11 (io), 75 I/O58 2B12 (io), 76 I/O59 2B13 (io), 81 I/O60 3B13 (io), 82 I/O61 3B12 (io), 83 I/O62 3B11 (io), 84 I/O63 3B8 (io), 86 I/O64 3B7 (io), 87 I/O65 3B6 (io), 88 I/O66 3B5 (io), 89 I/O67 3B4 (io), 90 I/O68 3B3 (io), 91 I/O69 3B2 (io), 92 I/O70 3B1 (io), 93 I/O71 3B0 (io), 96 I/O72 3A2 (io), 97 I/O73 3A3 (io), 98 I/O74 3A4 (io), 99 I/O75 3A7 (io), 100 I/O76 3A8 (io), 101 I/O77 3A11 (io), 102 I/O78 3A12 (io), 103 I/O79 3A13 (io), 106 I/O80 4A2 (io), 107 I/O81 4A3 (io), 108 I/O82 4A4 (io), 109 I/O83 4A7 (io), 110 I/O84 4A8 (io), 111 I/O85 4A11 (io), 112 I/O86 4A12 (io), 113 I/O87 4A13 (io), 116 I/O88 4D15 (io), 117 I/O89 4D14 (io), 118 I/O90 4D13 (io), 119 I/O91 4D12 (io), 120 I/O92 4D11 (io), 121 I/O93 4D10 (io), 122 I/O94 4D9 (io), 123 I/O95 4D8 (io), 125 I/O96 4D7 (io), 126 I/O97 4D4 (io), 127 I/O98 4D3 (io), 128 I/O99 4D2 (io), 133 I/O100 5D2 (io), 134 I/O101 5D3 (io), 135 I/O102 5D4 (io), 136 I/O103 5D7 (io), 138 I/O104 5D8 (io), 139 I/O105 5D9 (io), 140 I/O106 5D10 (io), 141 I/O107 5D11 (io), 142 I/O108 5D12 (io), 143 I/O109 5D13 (io), 144 I/O110 5D14 (io), 145 I/O111 5D15 (io), 148 I/O112 5A13 (io), 149 I/O113 5A12 (io), 150 I/O114 5A11 (io), 151 I/O115 5A8 (io), 152 I/O116 5A7 (io), 153 I/O117 5A4 (io), 154 I/O118 5A3 (io), 155 I/O119 5A2 (io), 158 I/O120 6A13 (io), 159 I/O121 6A12 (io), 160 I/O122 6A11 (io), 161 I/O123 6A8 (io), 162 I/O124 6A7 (io), 163 I/O125 6A4 (io), 164 I/O126 6A3 (io), 165 I/O127 6A2 (io), 168 I/O128 6B0 (io), 169 I/O129 6B1 (io), 170 I/O130 6B2 (io), 171 I/O131 6B3 (io), 172 I/O132 6B4 (io), 173 I/O133 6B5 (io), 174 I/O134 6B6 (io), 175 I/O135 6B7 (io), 177 I/O136 6B8 (io), 178 I/O137 6B11 (io), 179 I/O138 6B12 (io), 180 I/O139 6B13 (io), 185 I/O140 7B13 (io), 186 I/O141 7B12 (io), 187 I/O142 7B11 (io), 188 I/O143 7B8 (io), 190 I/O144 7B7 (io), 191 I/O145 7B6 (io), 192 I/O146 7B5 (io), 193 I/O147 7B4 (io), 194 I/O148 7B3 (io), 195 I/O149 7B2 (io), 196 I/O150 7B1 (io), 197 I/O151 7B0 (io), 200 I/O152 7A2 (io), 201 I/O153 7A3 (io), 202 I/O154 7A4 (io), 203 I/O155 7A7 (io), 204 I/O156 7A8 (io), 205 I/O157 7A11 (io), 206 I/O158 7A12 (io), 207 I/O159 7A13 (io)
part B pins: 1 TDI (in), 10 VCC (power), 11 GND (power), 20 GND (power), 25 I0/CLK0 (in), 26 VCC (power), 27 GND (power), 28 I1/CLK1 (in), 33 GND (power), 42 GND (power), 43 VCC (power), 52 TCK (in), 53 GND (power), 62 GND (power), 63 VCC (power), 72 GND (power), 77 VCC (power), 78 GND (power), 79 GND (power), 80 VCC (power), 85 GND (power), 94 VCC (power), 95 GND (power), 104 GND (power), 105 TMS (in), 114 VCC (power), 115 GND (power), 124 GND (power), 129 I2/CLK2 (in), 130 VCC (power), 131 GND (power), 132 I3/CLK3 (in), 137 GND (power), 146 GND (power), 147 VCC (power), 156 TDO (out), 157 GND (power), 166 GND (power), 167 VCC (power), 176 GND (power), 181 VCC (power), 182 GND (power), 183 GND (power), 184 VCC (power), 189 GND (power), 198 VCC (power), 199 GND (power), 208 GND (power)

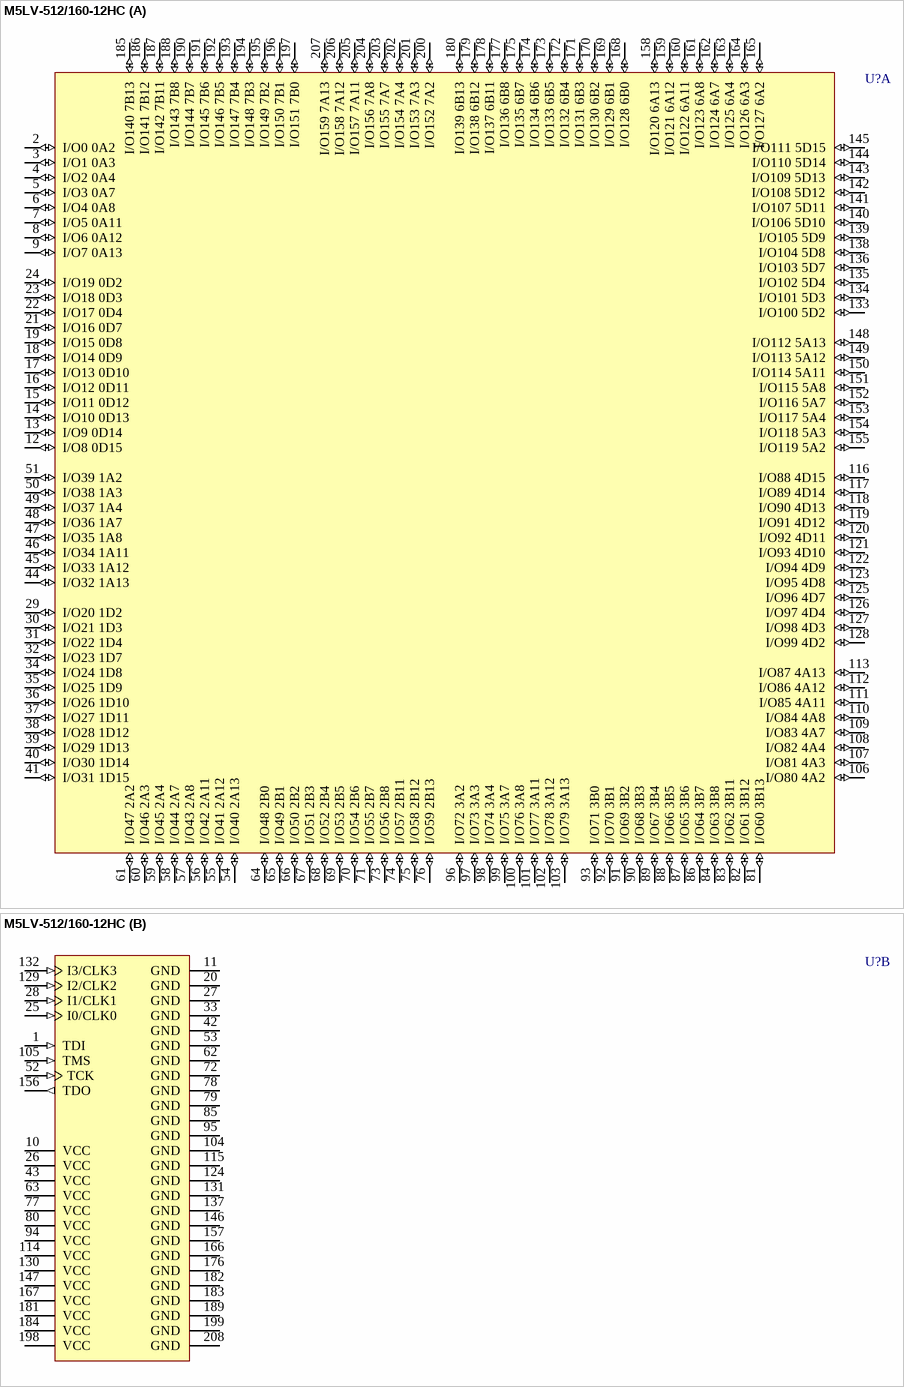
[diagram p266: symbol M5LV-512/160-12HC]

## M5LV-512/160-12HC
designator U?
High-Density and High-I/O Complex PLD
footprint MQFP208_N (Shrink QFP, 208-Leads, Body 27.7x27.7mm, Pitch 0.5mm, IPC Medium Density)
footprint MQFP208_L (Shrink QFP, 208-Leads, Body 27.7x27.7mm, Pitch 0.5mm, IPC High Density)
footprint MQFP208_M (Shrink QFP, 208-Leads, Body 27.7x27.7mm, Pitch 0.5mm, IPC Low Density)
3D model M5LV-MQFP208 (208-Pin Shrink Quad Flat Pack 0.5 mm Pitch)
part A pins: 2 I/O0 0A2 (io), 3 I/O1 0A3 (io), 4 I/O2 0A4 (io), 5 I/O3 0A7 (io), 6 I/O4 0A8 (io), 7 I/O5 0A11 (io), 8 I/O6 0A12 (io), 9 I/O7 0A13 (io), 12 I/O8 0D15 (io), 13 I/O9 0D14 (io), 14 I/O10 0D13 (io), 15 I/O11 0D12 (io), 16 I/O12 0D11 (io), 17 I/O13 0D10 (io), 18 I/O14 0D9 (io), 19 I/O15 0D8 (io), 21 I/O16 0D7 (io), 22 I/O17 0D4 (io), 23 I/O18 0D3 (io), 24 I/O19 0D2 (io), 29 I/O20 1D2 (io), 30 I/O21 1D3 (io), 31 I/O22 1D4 (io), 32 I/O23 1D7 (io), 34 I/O24 1D8 (io), 35 I/O25 1D9 (io), 36 I/O26 1D10 (io), 37 I/O27 1D11 (io), 38 I/O28 1D12 (io), 39 I/O29 1D13 (io), 40 I/O30 1D14 (io), 41 I/O31 1D15 (io), 44 I/O32 1A13 (io), 45 I/O33 1A12 (io), 46 I/O34 1A11 (io), 47 I/O35 1A8 (io), 48 I/O36 1A7 (io), 49 I/O37 1A4 (io), 50 I/O38 1A3 (io), 51 I/O39 1A2 (io), 54 I/O40 2A13 (io), 55 I/O41 2A12 (io), 56 I/O42 2A11 (io), 57 I/O43 2A8 (io), 58 I/O44 2A7 (io), 59 I/O45 2A4 (io), 60 I/O46 2A3 (io), 61 I/O47 2A2 (io), 64 I/O48 2B0 (io), 65 I/O49 2B1 (io), 66 I/O50 2B2 (io), 67 I/O51 2B3 (io), 68 I/O52 2B4 (io), 69 I/O53 2B5 (io), 70 I/O54 2B6 (io), 71 I/O55 2B7 (io), 73 I/O56 2B8 (io), 74 I/O57 2B11 (io), 75 I/O58 2B12 (io), 76 I/O59 2B13 (io), 81 I/O60 3B13 (io), 82 I/O61 3B12 (io), 83 I/O62 3B11 (io), 84 I/O63 3B8 (io), 86 I/O64 3B7 (io), 87 I/O65 3B6 (io), 88 I/O66 3B5 (io), 89 I/O67 3B4 (io), 90 I/O68 3B3 (io), 91 I/O69 3B2 (io), 92 I/O70 3B1 (io), 93 I/O71 3B0 (io), 96 I/O72 3A2 (io), 97 I/O73 3A3 (io), 98 I/O74 3A4 (io), 99 I/O75 3A7 (io), 100 I/O76 3A8 (io), 101 I/O77 3A11 (io), 102 I/O78 3A12 (io), 103 I/O79 3A13 (io), 106 I/O80 4A2 (io), 107 I/O81 4A3 (io), 108 I/O82 4A4 (io), 109 I/O83 4A7 (io), 110 I/O84 4A8 (io), 111 I/O85 4A11 (io), 112 I/O86 4A12 (io), 113 I/O87 4A13 (io), 116 I/O88 4D15 (io), 117 I/O89 4D14 (io), 118 I/O90 4D13 (io), 119 I/O91 4D12 (io), 120 I/O92 4D11 (io), 121 I/O93 4D10 (io), 122 I/O94 4D9 (io), 123 I/O95 4D8 (io), 125 I/O96 4D7 (io), 126 I/O97 4D4 (io), 127 I/O98 4D3 (io), 128 I/O99 4D2 (io), 133 I/O100 5D2 (io), 134 I/O101 5D3 (io), 135 I/O102 5D4 (io), 136 I/O103 5D7 (io), 138 I/O104 5D8 (io), 139 I/O105 5D9 (io), 140 I/O106 5D10 (io), 141 I/O107 5D11 (io), 142 I/O108 5D12 (io), 143 I/O109 5D13 (io), 144 I/O110 5D14 (io), 145 I/O111 5D15 (io), 148 I/O112 5A13 (io), 149 I/O113 5A12 (io), 150 I/O114 5A11 (io), 151 I/O115 5A8 (io), 152 I/O116 5A7 (io), 153 I/O117 5A4 (io), 154 I/O118 5A3 (io), 155 I/O119 5A2 (io), 158 I/O120 6A13 (io), 159 I/O121 6A12 (io), 160 I/O122 6A11 (io), 161 I/O123 6A8 (io), 162 I/O124 6A7 (io), 163 I/O125 6A4 (io), 164 I/O126 6A3 (io), 165 I/O127 6A2 (io), 168 I/O128 6B0 (io), 169 I/O129 6B1 (io), 170 I/O130 6B2 (io), 171 I/O131 6B3 (io), 172 I/O132 6B4 (io), 173 I/O133 6B5 (io), 174 I/O134 6B6 (io), 175 I/O135 6B7 (io), 177 I/O136 6B8 (io), 178 I/O137 6B11 (io), 179 I/O138 6B12 (io), 180 I/O139 6B13 (io), 185 I/O140 7B13 (io), 186 I/O141 7B12 (io), 187 I/O142 7B11 (io), 188 I/O143 7B8 (io), 190 I/O144 7B7 (io), 191 I/O145 7B6 (io), 192 I/O146 7B5 (io), 193 I/O147 7B4 (io), 194 I/O148 7B3 (io), 195 I/O149 7B2 (io), 196 I/O150 7B1 (io), 197 I/O151 7B0 (io), 200 I/O152 7A2 (io), 201 I/O153 7A3 (io), 202 I/O154 7A4 (io), 203 I/O155 7A7 (io), 204 I/O156 7A8 (io), 205 I/O157 7A11 (io), 206 I/O158 7A12 (io), 207 I/O159 7A13 (io)
part B pins: 1 TDI (in), 10 VCC (power), 11 GND (power), 20 GND (power), 25 I0/CLK0 (in), 26 VCC (power), 27 GND (power), 28 I1/CLK1 (in), 33 GND (power), 42 GND (power), 43 VCC (power), 52 TCK (in), 53 GND (power), 62 GND (power), 63 VCC (power), 72 GND (power), 77 VCC (power), 78 GND (power), 79 GND (power), 80 VCC (power), 85 GND (power), 94 VCC (power), 95 GND (power), 104 GND (power), 105 TMS (in), 114 VCC (power), 115 GND (power), 124 GND (power), 129 I2/CLK2 (in), 130 VCC (power), 131 GND (power), 132 I3/CLK3 (in), 137 GND (power), 146 GND (power), 147 VCC (power), 156 TDO (out), 157 GND (power), 166 GND (power), 167 VCC (power), 176 GND (power), 181 VCC (power), 182 GND (power), 183 GND (power), 184 VCC (power), 189 GND (power), 198 VCC (power), 199 GND (power), 208 GND (power)

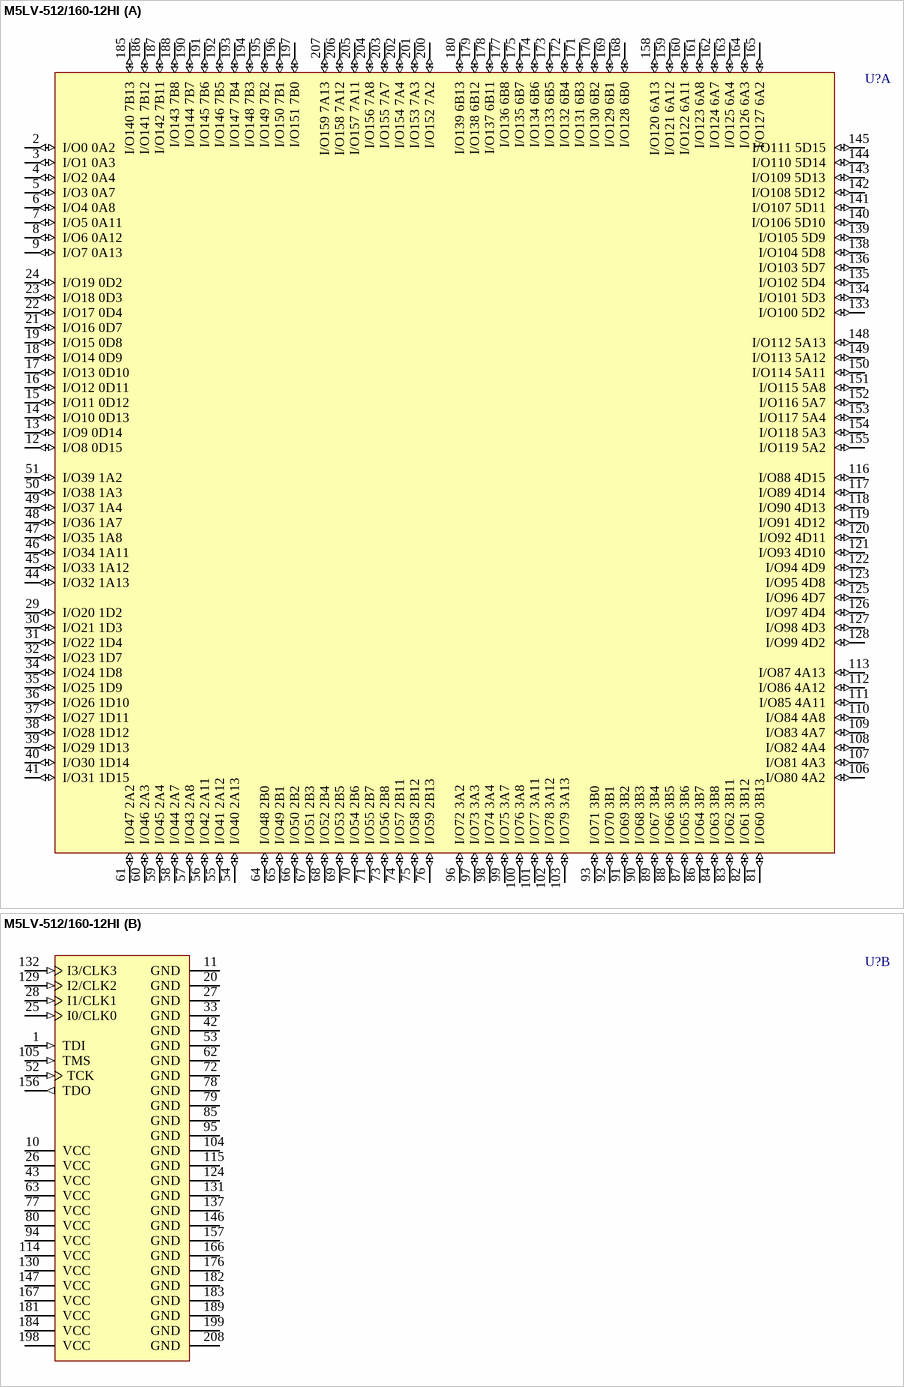
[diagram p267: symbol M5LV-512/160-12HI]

## M5LV-512/160-12HI
designator U?
High-Density and High-I/O Complex PLD
footprint MQFP208_N (Shrink QFP, 208-Leads, Body 27.7x27.7mm, Pitch 0.5mm, IPC Medium Density)
footprint MQFP208_L (Shrink QFP, 208-Leads, Body 27.7x27.7mm, Pitch 0.5mm, IPC High Density)
footprint MQFP208_M (Shrink QFP, 208-Leads, Body 27.7x27.7mm, Pitch 0.5mm, IPC Low Density)
3D model M5LV-MQFP208 (208-Pin Shrink Quad Flat Pack 0.5 mm Pitch)
part A pins: 2 I/O0 0A2 (io), 3 I/O1 0A3 (io), 4 I/O2 0A4 (io), 5 I/O3 0A7 (io), 6 I/O4 0A8 (io), 7 I/O5 0A11 (io), 8 I/O6 0A12 (io), 9 I/O7 0A13 (io), 12 I/O8 0D15 (io), 13 I/O9 0D14 (io), 14 I/O10 0D13 (io), 15 I/O11 0D12 (io), 16 I/O12 0D11 (io), 17 I/O13 0D10 (io), 18 I/O14 0D9 (io), 19 I/O15 0D8 (io), 21 I/O16 0D7 (io), 22 I/O17 0D4 (io), 23 I/O18 0D3 (io), 24 I/O19 0D2 (io), 29 I/O20 1D2 (io), 30 I/O21 1D3 (io), 31 I/O22 1D4 (io), 32 I/O23 1D7 (io), 34 I/O24 1D8 (io), 35 I/O25 1D9 (io), 36 I/O26 1D10 (io), 37 I/O27 1D11 (io), 38 I/O28 1D12 (io), 39 I/O29 1D13 (io), 40 I/O30 1D14 (io), 41 I/O31 1D15 (io), 44 I/O32 1A13 (io), 45 I/O33 1A12 (io), 46 I/O34 1A11 (io), 47 I/O35 1A8 (io), 48 I/O36 1A7 (io), 49 I/O37 1A4 (io), 50 I/O38 1A3 (io), 51 I/O39 1A2 (io), 54 I/O40 2A13 (io), 55 I/O41 2A12 (io), 56 I/O42 2A11 (io), 57 I/O43 2A8 (io), 58 I/O44 2A7 (io), 59 I/O45 2A4 (io), 60 I/O46 2A3 (io), 61 I/O47 2A2 (io), 64 I/O48 2B0 (io), 65 I/O49 2B1 (io), 66 I/O50 2B2 (io), 67 I/O51 2B3 (io), 68 I/O52 2B4 (io), 69 I/O53 2B5 (io), 70 I/O54 2B6 (io), 71 I/O55 2B7 (io), 73 I/O56 2B8 (io), 74 I/O57 2B11 (io), 75 I/O58 2B12 (io), 76 I/O59 2B13 (io), 81 I/O60 3B13 (io), 82 I/O61 3B12 (io), 83 I/O62 3B11 (io), 84 I/O63 3B8 (io), 86 I/O64 3B7 (io), 87 I/O65 3B6 (io), 88 I/O66 3B5 (io), 89 I/O67 3B4 (io), 90 I/O68 3B3 (io), 91 I/O69 3B2 (io), 92 I/O70 3B1 (io), 93 I/O71 3B0 (io), 96 I/O72 3A2 (io), 97 I/O73 3A3 (io), 98 I/O74 3A4 (io), 99 I/O75 3A7 (io), 100 I/O76 3A8 (io), 101 I/O77 3A11 (io), 102 I/O78 3A12 (io), 103 I/O79 3A13 (io), 106 I/O80 4A2 (io), 107 I/O81 4A3 (io), 108 I/O82 4A4 (io), 109 I/O83 4A7 (io), 110 I/O84 4A8 (io), 111 I/O85 4A11 (io), 112 I/O86 4A12 (io), 113 I/O87 4A13 (io), 116 I/O88 4D15 (io), 117 I/O89 4D14 (io), 118 I/O90 4D13 (io), 119 I/O91 4D12 (io), 120 I/O92 4D11 (io), 121 I/O93 4D10 (io), 122 I/O94 4D9 (io), 123 I/O95 4D8 (io), 125 I/O96 4D7 (io), 126 I/O97 4D4 (io), 127 I/O98 4D3 (io), 128 I/O99 4D2 (io), 133 I/O100 5D2 (io), 134 I/O101 5D3 (io), 135 I/O102 5D4 (io), 136 I/O103 5D7 (io), 138 I/O104 5D8 (io), 139 I/O105 5D9 (io), 140 I/O106 5D10 (io), 141 I/O107 5D11 (io), 142 I/O108 5D12 (io), 143 I/O109 5D13 (io), 144 I/O110 5D14 (io), 145 I/O111 5D15 (io), 148 I/O112 5A13 (io), 149 I/O113 5A12 (io), 150 I/O114 5A11 (io), 151 I/O115 5A8 (io), 152 I/O116 5A7 (io), 153 I/O117 5A4 (io), 154 I/O118 5A3 (io), 155 I/O119 5A2 (io), 158 I/O120 6A13 (io), 159 I/O121 6A12 (io), 160 I/O122 6A11 (io), 161 I/O123 6A8 (io), 162 I/O124 6A7 (io), 163 I/O125 6A4 (io), 164 I/O126 6A3 (io), 165 I/O127 6A2 (io), 168 I/O128 6B0 (io), 169 I/O129 6B1 (io), 170 I/O130 6B2 (io), 171 I/O131 6B3 (io), 172 I/O132 6B4 (io), 173 I/O133 6B5 (io), 174 I/O134 6B6 (io), 175 I/O135 6B7 (io), 177 I/O136 6B8 (io), 178 I/O137 6B11 (io), 179 I/O138 6B12 (io), 180 I/O139 6B13 (io), 185 I/O140 7B13 (io), 186 I/O141 7B12 (io), 187 I/O142 7B11 (io), 188 I/O143 7B8 (io), 190 I/O144 7B7 (io), 191 I/O145 7B6 (io), 192 I/O146 7B5 (io), 193 I/O147 7B4 (io), 194 I/O148 7B3 (io), 195 I/O149 7B2 (io), 196 I/O150 7B1 (io), 197 I/O151 7B0 (io), 200 I/O152 7A2 (io), 201 I/O153 7A3 (io), 202 I/O154 7A4 (io), 203 I/O155 7A7 (io), 204 I/O156 7A8 (io), 205 I/O157 7A11 (io), 206 I/O158 7A12 (io), 207 I/O159 7A13 (io)
part B pins: 1 TDI (in), 10 VCC (power), 11 GND (power), 20 GND (power), 25 I0/CLK0 (in), 26 VCC (power), 27 GND (power), 28 I1/CLK1 (in), 33 GND (power), 42 GND (power), 43 VCC (power), 52 TCK (in), 53 GND (power), 62 GND (power), 63 VCC (power), 72 GND (power), 77 VCC (power), 78 GND (power), 79 GND (power), 80 VCC (power), 85 GND (power), 94 VCC (power), 95 GND (power), 104 GND (power), 105 TMS (in), 114 VCC (power), 115 GND (power), 124 GND (power), 129 I2/CLK2 (in), 130 VCC (power), 131 GND (power), 132 I3/CLK3 (in), 137 GND (power), 146 GND (power), 147 VCC (power), 156 TDO (out), 157 GND (power), 166 GND (power), 167 VCC (power), 176 GND (power), 181 VCC (power), 182 GND (power), 183 GND (power), 184 VCC (power), 189 GND (power), 198 VCC (power), 199 GND (power), 208 GND (power)

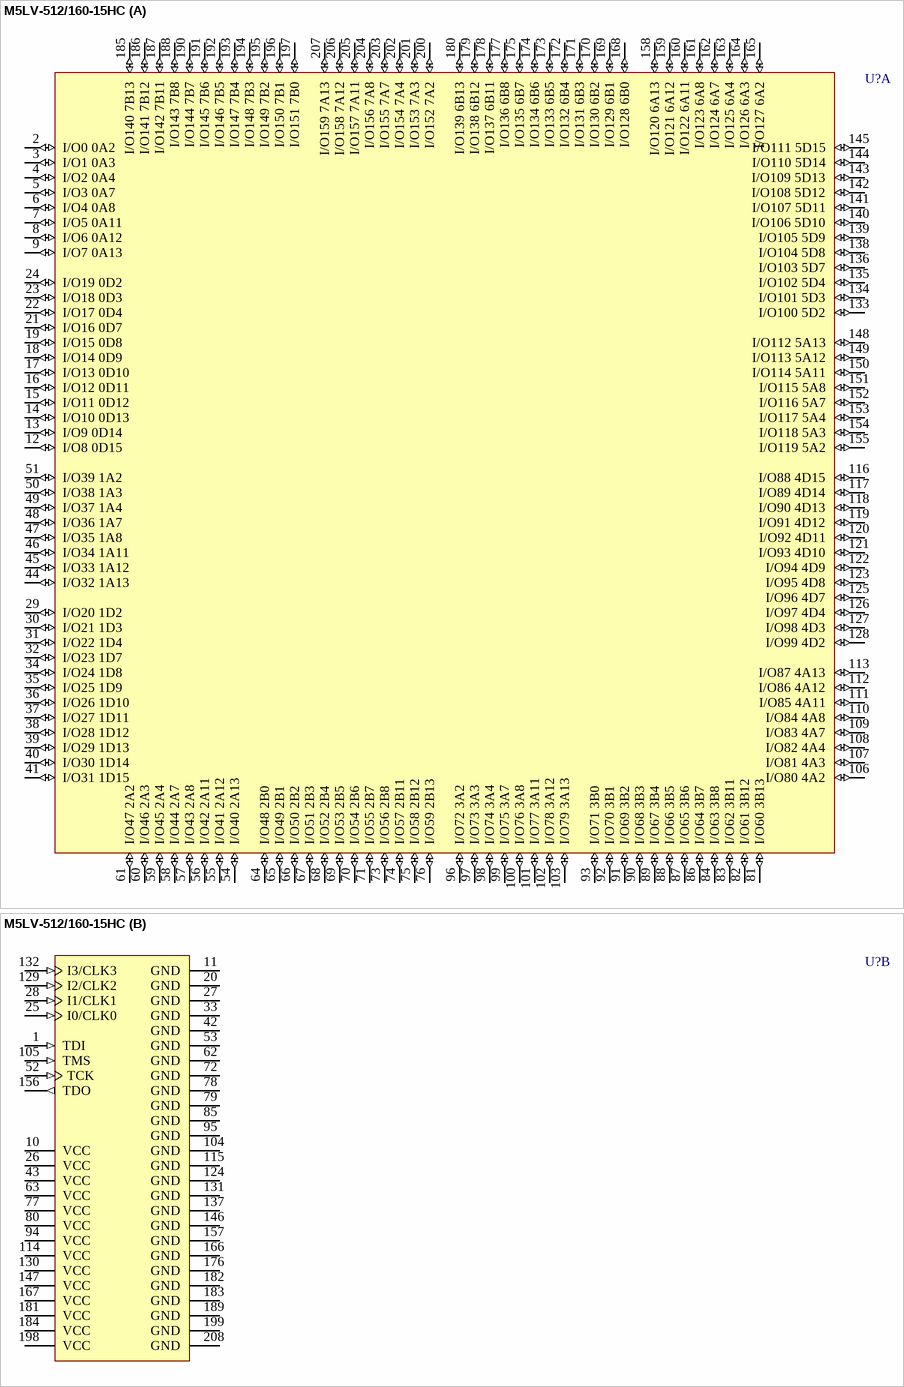
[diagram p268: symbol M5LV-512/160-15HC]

## M5LV-512/160-15HC
designator U?
High-Density and High-I/O Complex PLD
footprint MQFP208_N (Shrink QFP, 208-Leads, Body 27.7x27.7mm, Pitch 0.5mm, IPC Medium Density)
footprint MQFP208_L (Shrink QFP, 208-Leads, Body 27.7x27.7mm, Pitch 0.5mm, IPC High Density)
footprint MQFP208_M (Shrink QFP, 208-Leads, Body 27.7x27.7mm, Pitch 0.5mm, IPC Low Density)
3D model M5LV-MQFP208 (208-Pin Shrink Quad Flat Pack 0.5 mm Pitch)
part A pins: 2 I/O0 0A2 (io), 3 I/O1 0A3 (io), 4 I/O2 0A4 (io), 5 I/O3 0A7 (io), 6 I/O4 0A8 (io), 7 I/O5 0A11 (io), 8 I/O6 0A12 (io), 9 I/O7 0A13 (io), 12 I/O8 0D15 (io), 13 I/O9 0D14 (io), 14 I/O10 0D13 (io), 15 I/O11 0D12 (io), 16 I/O12 0D11 (io), 17 I/O13 0D10 (io), 18 I/O14 0D9 (io), 19 I/O15 0D8 (io), 21 I/O16 0D7 (io), 22 I/O17 0D4 (io), 23 I/O18 0D3 (io), 24 I/O19 0D2 (io), 29 I/O20 1D2 (io), 30 I/O21 1D3 (io), 31 I/O22 1D4 (io), 32 I/O23 1D7 (io), 34 I/O24 1D8 (io), 35 I/O25 1D9 (io), 36 I/O26 1D10 (io), 37 I/O27 1D11 (io), 38 I/O28 1D12 (io), 39 I/O29 1D13 (io), 40 I/O30 1D14 (io), 41 I/O31 1D15 (io), 44 I/O32 1A13 (io), 45 I/O33 1A12 (io), 46 I/O34 1A11 (io), 47 I/O35 1A8 (io), 48 I/O36 1A7 (io), 49 I/O37 1A4 (io), 50 I/O38 1A3 (io), 51 I/O39 1A2 (io), 54 I/O40 2A13 (io), 55 I/O41 2A12 (io), 56 I/O42 2A11 (io), 57 I/O43 2A8 (io), 58 I/O44 2A7 (io), 59 I/O45 2A4 (io), 60 I/O46 2A3 (io), 61 I/O47 2A2 (io), 64 I/O48 2B0 (io), 65 I/O49 2B1 (io), 66 I/O50 2B2 (io), 67 I/O51 2B3 (io), 68 I/O52 2B4 (io), 69 I/O53 2B5 (io), 70 I/O54 2B6 (io), 71 I/O55 2B7 (io), 73 I/O56 2B8 (io), 74 I/O57 2B11 (io), 75 I/O58 2B12 (io), 76 I/O59 2B13 (io), 81 I/O60 3B13 (io), 82 I/O61 3B12 (io), 83 I/O62 3B11 (io), 84 I/O63 3B8 (io), 86 I/O64 3B7 (io), 87 I/O65 3B6 (io), 88 I/O66 3B5 (io), 89 I/O67 3B4 (io), 90 I/O68 3B3 (io), 91 I/O69 3B2 (io), 92 I/O70 3B1 (io), 93 I/O71 3B0 (io), 96 I/O72 3A2 (io), 97 I/O73 3A3 (io), 98 I/O74 3A4 (io), 99 I/O75 3A7 (io), 100 I/O76 3A8 (io), 101 I/O77 3A11 (io), 102 I/O78 3A12 (io), 103 I/O79 3A13 (io), 106 I/O80 4A2 (io), 107 I/O81 4A3 (io), 108 I/O82 4A4 (io), 109 I/O83 4A7 (io), 110 I/O84 4A8 (io), 111 I/O85 4A11 (io), 112 I/O86 4A12 (io), 113 I/O87 4A13 (io), 116 I/O88 4D15 (io), 117 I/O89 4D14 (io), 118 I/O90 4D13 (io), 119 I/O91 4D12 (io), 120 I/O92 4D11 (io), 121 I/O93 4D10 (io), 122 I/O94 4D9 (io), 123 I/O95 4D8 (io), 125 I/O96 4D7 (io), 126 I/O97 4D4 (io), 127 I/O98 4D3 (io), 128 I/O99 4D2 (io), 133 I/O100 5D2 (io), 134 I/O101 5D3 (io), 135 I/O102 5D4 (io), 136 I/O103 5D7 (io), 138 I/O104 5D8 (io), 139 I/O105 5D9 (io), 140 I/O106 5D10 (io), 141 I/O107 5D11 (io), 142 I/O108 5D12 (io), 143 I/O109 5D13 (io), 144 I/O110 5D14 (io), 145 I/O111 5D15 (io), 148 I/O112 5A13 (io), 149 I/O113 5A12 (io), 150 I/O114 5A11 (io), 151 I/O115 5A8 (io), 152 I/O116 5A7 (io), 153 I/O117 5A4 (io), 154 I/O118 5A3 (io), 155 I/O119 5A2 (io), 158 I/O120 6A13 (io), 159 I/O121 6A12 (io), 160 I/O122 6A11 (io), 161 I/O123 6A8 (io), 162 I/O124 6A7 (io), 163 I/O125 6A4 (io), 164 I/O126 6A3 (io), 165 I/O127 6A2 (io), 168 I/O128 6B0 (io), 169 I/O129 6B1 (io), 170 I/O130 6B2 (io), 171 I/O131 6B3 (io), 172 I/O132 6B4 (io), 173 I/O133 6B5 (io), 174 I/O134 6B6 (io), 175 I/O135 6B7 (io), 177 I/O136 6B8 (io), 178 I/O137 6B11 (io), 179 I/O138 6B12 (io), 180 I/O139 6B13 (io), 185 I/O140 7B13 (io), 186 I/O141 7B12 (io), 187 I/O142 7B11 (io), 188 I/O143 7B8 (io), 190 I/O144 7B7 (io), 191 I/O145 7B6 (io), 192 I/O146 7B5 (io), 193 I/O147 7B4 (io), 194 I/O148 7B3 (io), 195 I/O149 7B2 (io), 196 I/O150 7B1 (io), 197 I/O151 7B0 (io), 200 I/O152 7A2 (io), 201 I/O153 7A3 (io), 202 I/O154 7A4 (io), 203 I/O155 7A7 (io), 204 I/O156 7A8 (io), 205 I/O157 7A11 (io), 206 I/O158 7A12 (io), 207 I/O159 7A13 (io)
part B pins: 1 TDI (in), 10 VCC (power), 11 GND (power), 20 GND (power), 25 I0/CLK0 (in), 26 VCC (power), 27 GND (power), 28 I1/CLK1 (in), 33 GND (power), 42 GND (power), 43 VCC (power), 52 TCK (in), 53 GND (power), 62 GND (power), 63 VCC (power), 72 GND (power), 77 VCC (power), 78 GND (power), 79 GND (power), 80 VCC (power), 85 GND (power), 94 VCC (power), 95 GND (power), 104 GND (power), 105 TMS (in), 114 VCC (power), 115 GND (power), 124 GND (power), 129 I2/CLK2 (in), 130 VCC (power), 131 GND (power), 132 I3/CLK3 (in), 137 GND (power), 146 GND (power), 147 VCC (power), 156 TDO (out), 157 GND (power), 166 GND (power), 167 VCC (power), 176 GND (power), 181 VCC (power), 182 GND (power), 183 GND (power), 184 VCC (power), 189 GND (power), 198 VCC (power), 199 GND (power), 208 GND (power)

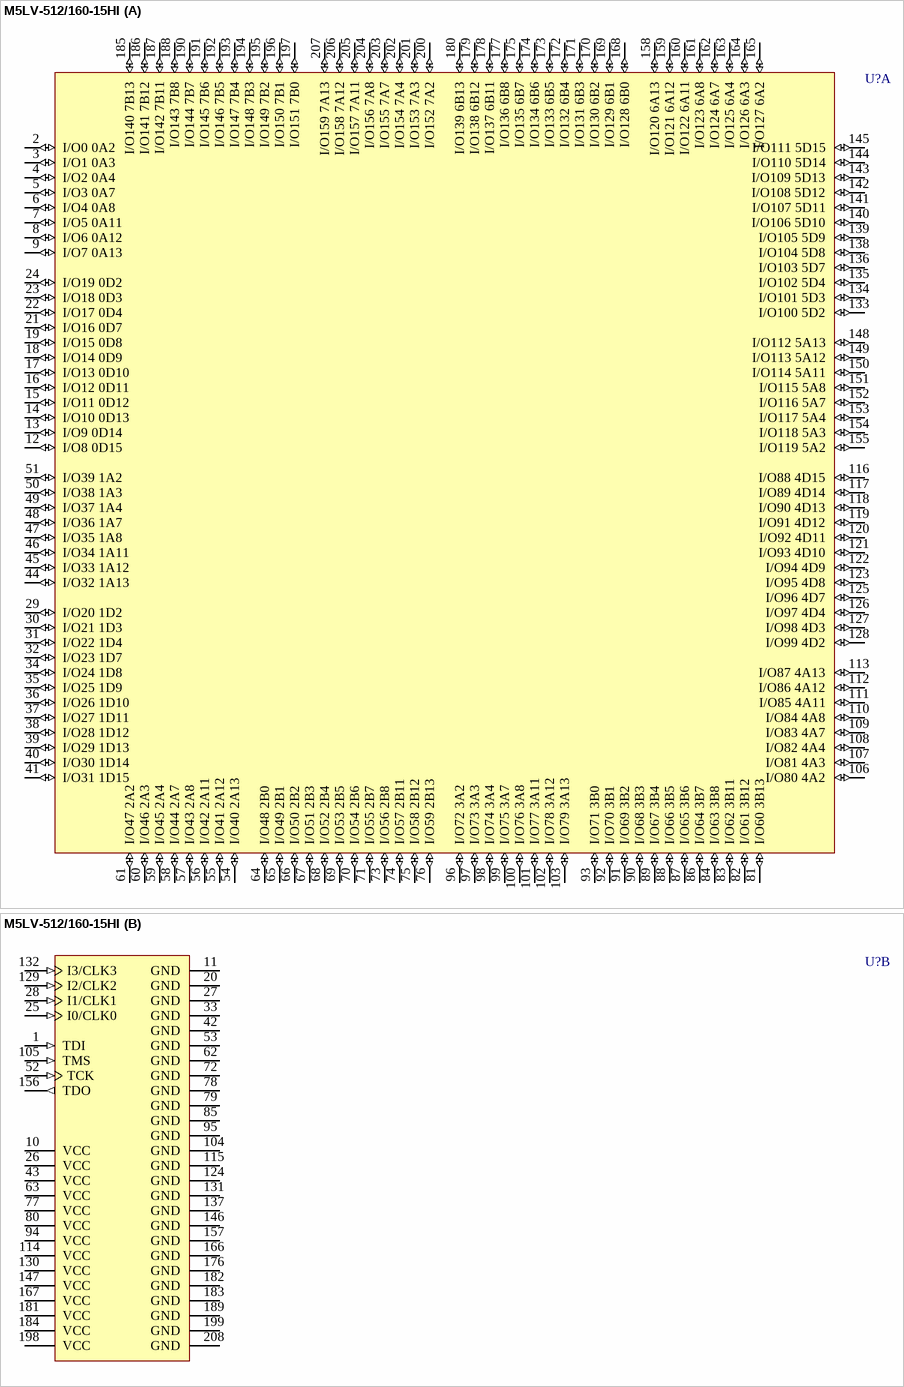
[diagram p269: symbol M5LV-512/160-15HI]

## M5LV-512/160-15HI
designator U?
High-Density and High-I/O Complex PLD
footprint MQFP208_N (Shrink QFP, 208-Leads, Body 27.7x27.7mm, Pitch 0.5mm, IPC Medium Density)
footprint MQFP208_L (Shrink QFP, 208-Leads, Body 27.7x27.7mm, Pitch 0.5mm, IPC High Density)
footprint MQFP208_M (Shrink QFP, 208-Leads, Body 27.7x27.7mm, Pitch 0.5mm, IPC Low Density)
3D model M5LV-MQFP208 (208-Pin Shrink Quad Flat Pack 0.5 mm Pitch)
part A pins: 2 I/O0 0A2 (io), 3 I/O1 0A3 (io), 4 I/O2 0A4 (io), 5 I/O3 0A7 (io), 6 I/O4 0A8 (io), 7 I/O5 0A11 (io), 8 I/O6 0A12 (io), 9 I/O7 0A13 (io), 12 I/O8 0D15 (io), 13 I/O9 0D14 (io), 14 I/O10 0D13 (io), 15 I/O11 0D12 (io), 16 I/O12 0D11 (io), 17 I/O13 0D10 (io), 18 I/O14 0D9 (io), 19 I/O15 0D8 (io), 21 I/O16 0D7 (io), 22 I/O17 0D4 (io), 23 I/O18 0D3 (io), 24 I/O19 0D2 (io), 29 I/O20 1D2 (io), 30 I/O21 1D3 (io), 31 I/O22 1D4 (io), 32 I/O23 1D7 (io), 34 I/O24 1D8 (io), 35 I/O25 1D9 (io), 36 I/O26 1D10 (io), 37 I/O27 1D11 (io), 38 I/O28 1D12 (io), 39 I/O29 1D13 (io), 40 I/O30 1D14 (io), 41 I/O31 1D15 (io), 44 I/O32 1A13 (io), 45 I/O33 1A12 (io), 46 I/O34 1A11 (io), 47 I/O35 1A8 (io), 48 I/O36 1A7 (io), 49 I/O37 1A4 (io), 50 I/O38 1A3 (io), 51 I/O39 1A2 (io), 54 I/O40 2A13 (io), 55 I/O41 2A12 (io), 56 I/O42 2A11 (io), 57 I/O43 2A8 (io), 58 I/O44 2A7 (io), 59 I/O45 2A4 (io), 60 I/O46 2A3 (io), 61 I/O47 2A2 (io), 64 I/O48 2B0 (io), 65 I/O49 2B1 (io), 66 I/O50 2B2 (io), 67 I/O51 2B3 (io), 68 I/O52 2B4 (io), 69 I/O53 2B5 (io), 70 I/O54 2B6 (io), 71 I/O55 2B7 (io), 73 I/O56 2B8 (io), 74 I/O57 2B11 (io), 75 I/O58 2B12 (io), 76 I/O59 2B13 (io), 81 I/O60 3B13 (io), 82 I/O61 3B12 (io), 83 I/O62 3B11 (io), 84 I/O63 3B8 (io), 86 I/O64 3B7 (io), 87 I/O65 3B6 (io), 88 I/O66 3B5 (io), 89 I/O67 3B4 (io), 90 I/O68 3B3 (io), 91 I/O69 3B2 (io), 92 I/O70 3B1 (io), 93 I/O71 3B0 (io), 96 I/O72 3A2 (io), 97 I/O73 3A3 (io), 98 I/O74 3A4 (io), 99 I/O75 3A7 (io), 100 I/O76 3A8 (io), 101 I/O77 3A11 (io), 102 I/O78 3A12 (io), 103 I/O79 3A13 (io), 106 I/O80 4A2 (io), 107 I/O81 4A3 (io), 108 I/O82 4A4 (io), 109 I/O83 4A7 (io), 110 I/O84 4A8 (io), 111 I/O85 4A11 (io), 112 I/O86 4A12 (io), 113 I/O87 4A13 (io), 116 I/O88 4D15 (io), 117 I/O89 4D14 (io), 118 I/O90 4D13 (io), 119 I/O91 4D12 (io), 120 I/O92 4D11 (io), 121 I/O93 4D10 (io), 122 I/O94 4D9 (io), 123 I/O95 4D8 (io), 125 I/O96 4D7 (io), 126 I/O97 4D4 (io), 127 I/O98 4D3 (io), 128 I/O99 4D2 (io), 133 I/O100 5D2 (io), 134 I/O101 5D3 (io), 135 I/O102 5D4 (io), 136 I/O103 5D7 (io), 138 I/O104 5D8 (io), 139 I/O105 5D9 (io), 140 I/O106 5D10 (io), 141 I/O107 5D11 (io), 142 I/O108 5D12 (io), 143 I/O109 5D13 (io), 144 I/O110 5D14 (io), 145 I/O111 5D15 (io), 148 I/O112 5A13 (io), 149 I/O113 5A12 (io), 150 I/O114 5A11 (io), 151 I/O115 5A8 (io), 152 I/O116 5A7 (io), 153 I/O117 5A4 (io), 154 I/O118 5A3 (io), 155 I/O119 5A2 (io), 158 I/O120 6A13 (io), 159 I/O121 6A12 (io), 160 I/O122 6A11 (io), 161 I/O123 6A8 (io), 162 I/O124 6A7 (io), 163 I/O125 6A4 (io), 164 I/O126 6A3 (io), 165 I/O127 6A2 (io), 168 I/O128 6B0 (io), 169 I/O129 6B1 (io), 170 I/O130 6B2 (io), 171 I/O131 6B3 (io), 172 I/O132 6B4 (io), 173 I/O133 6B5 (io), 174 I/O134 6B6 (io), 175 I/O135 6B7 (io), 177 I/O136 6B8 (io), 178 I/O137 6B11 (io), 179 I/O138 6B12 (io), 180 I/O139 6B13 (io), 185 I/O140 7B13 (io), 186 I/O141 7B12 (io), 187 I/O142 7B11 (io), 188 I/O143 7B8 (io), 190 I/O144 7B7 (io), 191 I/O145 7B6 (io), 192 I/O146 7B5 (io), 193 I/O147 7B4 (io), 194 I/O148 7B3 (io), 195 I/O149 7B2 (io), 196 I/O150 7B1 (io), 197 I/O151 7B0 (io), 200 I/O152 7A2 (io), 201 I/O153 7A3 (io), 202 I/O154 7A4 (io), 203 I/O155 7A7 (io), 204 I/O156 7A8 (io), 205 I/O157 7A11 (io), 206 I/O158 7A12 (io), 207 I/O159 7A13 (io)
part B pins: 1 TDI (in), 10 VCC (power), 11 GND (power), 20 GND (power), 25 I0/CLK0 (in), 26 VCC (power), 27 GND (power), 28 I1/CLK1 (in), 33 GND (power), 42 GND (power), 43 VCC (power), 52 TCK (in), 53 GND (power), 62 GND (power), 63 VCC (power), 72 GND (power), 77 VCC (power), 78 GND (power), 79 GND (power), 80 VCC (power), 85 GND (power), 94 VCC (power), 95 GND (power), 104 GND (power), 105 TMS (in), 114 VCC (power), 115 GND (power), 124 GND (power), 129 I2/CLK2 (in), 130 VCC (power), 131 GND (power), 132 I3/CLK3 (in), 137 GND (power), 146 GND (power), 147 VCC (power), 156 TDO (out), 157 GND (power), 166 GND (power), 167 VCC (power), 176 GND (power), 181 VCC (power), 182 GND (power), 183 GND (power), 184 VCC (power), 189 GND (power), 198 VCC (power), 199 GND (power), 208 GND (power)

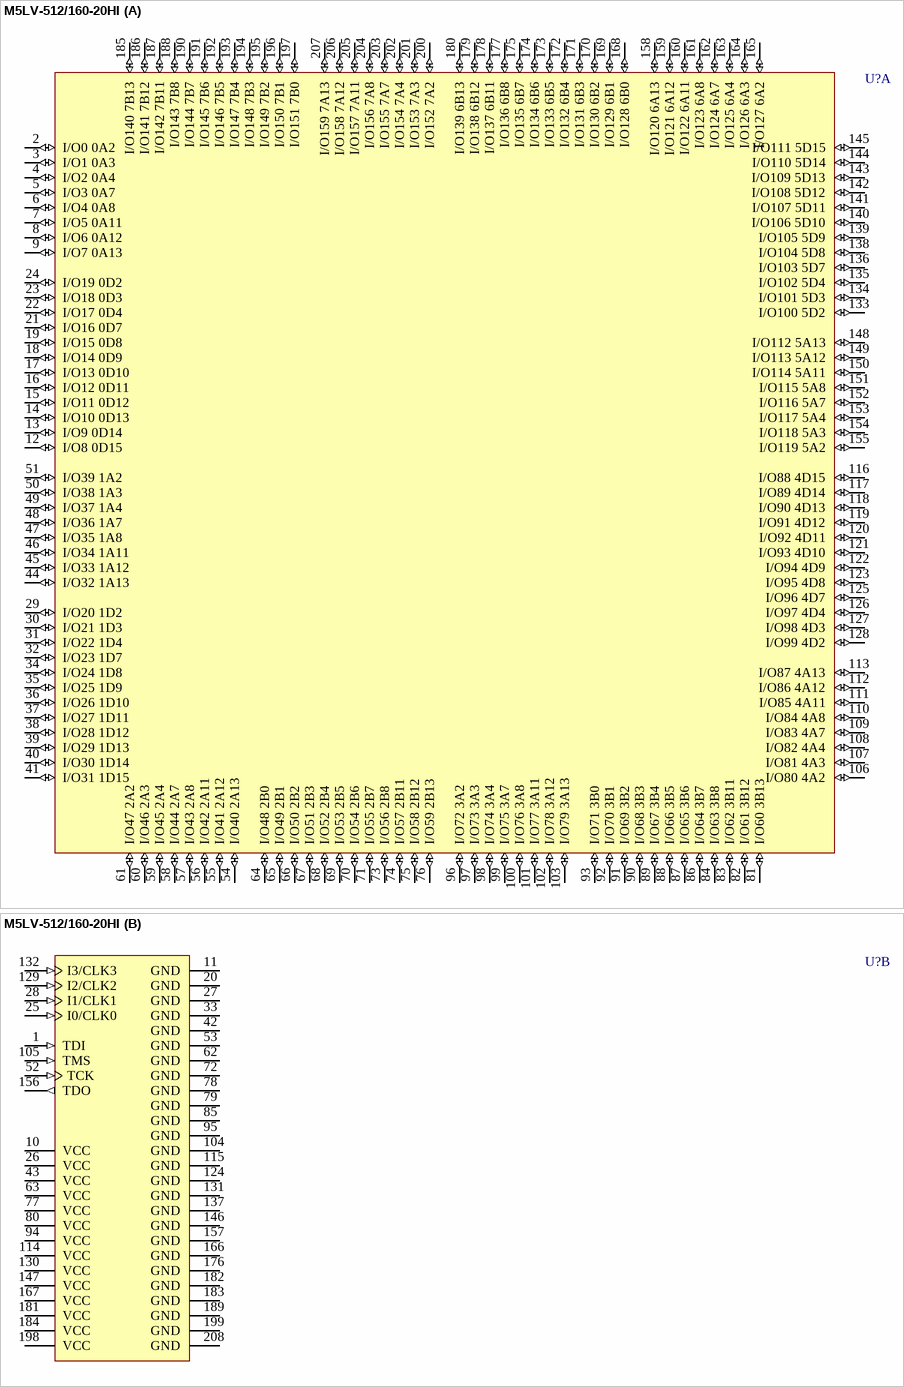
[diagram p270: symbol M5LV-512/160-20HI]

## M5LV-512/160-20HI
designator U?
High-Density and High-I/O Complex PLD
footprint MQFP208_N (Shrink QFP, 208-Leads, Body 27.7x27.7mm, Pitch 0.5mm, IPC Medium Density)
footprint MQFP208_L (Shrink QFP, 208-Leads, Body 27.7x27.7mm, Pitch 0.5mm, IPC High Density)
footprint MQFP208_M (Shrink QFP, 208-Leads, Body 27.7x27.7mm, Pitch 0.5mm, IPC Low Density)
3D model M5LV-MQFP208 (208-Pin Shrink Quad Flat Pack 0.5 mm Pitch)
part A pins: 2 I/O0 0A2 (io), 3 I/O1 0A3 (io), 4 I/O2 0A4 (io), 5 I/O3 0A7 (io), 6 I/O4 0A8 (io), 7 I/O5 0A11 (io), 8 I/O6 0A12 (io), 9 I/O7 0A13 (io), 12 I/O8 0D15 (io), 13 I/O9 0D14 (io), 14 I/O10 0D13 (io), 15 I/O11 0D12 (io), 16 I/O12 0D11 (io), 17 I/O13 0D10 (io), 18 I/O14 0D9 (io), 19 I/O15 0D8 (io), 21 I/O16 0D7 (io), 22 I/O17 0D4 (io), 23 I/O18 0D3 (io), 24 I/O19 0D2 (io), 29 I/O20 1D2 (io), 30 I/O21 1D3 (io), 31 I/O22 1D4 (io), 32 I/O23 1D7 (io), 34 I/O24 1D8 (io), 35 I/O25 1D9 (io), 36 I/O26 1D10 (io), 37 I/O27 1D11 (io), 38 I/O28 1D12 (io), 39 I/O29 1D13 (io), 40 I/O30 1D14 (io), 41 I/O31 1D15 (io), 44 I/O32 1A13 (io), 45 I/O33 1A12 (io), 46 I/O34 1A11 (io), 47 I/O35 1A8 (io), 48 I/O36 1A7 (io), 49 I/O37 1A4 (io), 50 I/O38 1A3 (io), 51 I/O39 1A2 (io), 54 I/O40 2A13 (io), 55 I/O41 2A12 (io), 56 I/O42 2A11 (io), 57 I/O43 2A8 (io), 58 I/O44 2A7 (io), 59 I/O45 2A4 (io), 60 I/O46 2A3 (io), 61 I/O47 2A2 (io), 64 I/O48 2B0 (io), 65 I/O49 2B1 (io), 66 I/O50 2B2 (io), 67 I/O51 2B3 (io), 68 I/O52 2B4 (io), 69 I/O53 2B5 (io), 70 I/O54 2B6 (io), 71 I/O55 2B7 (io), 73 I/O56 2B8 (io), 74 I/O57 2B11 (io), 75 I/O58 2B12 (io), 76 I/O59 2B13 (io), 81 I/O60 3B13 (io), 82 I/O61 3B12 (io), 83 I/O62 3B11 (io), 84 I/O63 3B8 (io), 86 I/O64 3B7 (io), 87 I/O65 3B6 (io), 88 I/O66 3B5 (io), 89 I/O67 3B4 (io), 90 I/O68 3B3 (io), 91 I/O69 3B2 (io), 92 I/O70 3B1 (io), 93 I/O71 3B0 (io), 96 I/O72 3A2 (io), 97 I/O73 3A3 (io), 98 I/O74 3A4 (io), 99 I/O75 3A7 (io), 100 I/O76 3A8 (io), 101 I/O77 3A11 (io), 102 I/O78 3A12 (io), 103 I/O79 3A13 (io), 106 I/O80 4A2 (io), 107 I/O81 4A3 (io), 108 I/O82 4A4 (io), 109 I/O83 4A7 (io), 110 I/O84 4A8 (io), 111 I/O85 4A11 (io), 112 I/O86 4A12 (io), 113 I/O87 4A13 (io), 116 I/O88 4D15 (io), 117 I/O89 4D14 (io), 118 I/O90 4D13 (io), 119 I/O91 4D12 (io), 120 I/O92 4D11 (io), 121 I/O93 4D10 (io), 122 I/O94 4D9 (io), 123 I/O95 4D8 (io), 125 I/O96 4D7 (io), 126 I/O97 4D4 (io), 127 I/O98 4D3 (io), 128 I/O99 4D2 (io), 133 I/O100 5D2 (io), 134 I/O101 5D3 (io), 135 I/O102 5D4 (io), 136 I/O103 5D7 (io), 138 I/O104 5D8 (io), 139 I/O105 5D9 (io), 140 I/O106 5D10 (io), 141 I/O107 5D11 (io), 142 I/O108 5D12 (io), 143 I/O109 5D13 (io), 144 I/O110 5D14 (io), 145 I/O111 5D15 (io), 148 I/O112 5A13 (io), 149 I/O113 5A12 (io), 150 I/O114 5A11 (io), 151 I/O115 5A8 (io), 152 I/O116 5A7 (io), 153 I/O117 5A4 (io), 154 I/O118 5A3 (io), 155 I/O119 5A2 (io), 158 I/O120 6A13 (io), 159 I/O121 6A12 (io), 160 I/O122 6A11 (io), 161 I/O123 6A8 (io), 162 I/O124 6A7 (io), 163 I/O125 6A4 (io), 164 I/O126 6A3 (io), 165 I/O127 6A2 (io), 168 I/O128 6B0 (io), 169 I/O129 6B1 (io), 170 I/O130 6B2 (io), 171 I/O131 6B3 (io), 172 I/O132 6B4 (io), 173 I/O133 6B5 (io), 174 I/O134 6B6 (io), 175 I/O135 6B7 (io), 177 I/O136 6B8 (io), 178 I/O137 6B11 (io), 179 I/O138 6B12 (io), 180 I/O139 6B13 (io), 185 I/O140 7B13 (io), 186 I/O141 7B12 (io), 187 I/O142 7B11 (io), 188 I/O143 7B8 (io), 190 I/O144 7B7 (io), 191 I/O145 7B6 (io), 192 I/O146 7B5 (io), 193 I/O147 7B4 (io), 194 I/O148 7B3 (io), 195 I/O149 7B2 (io), 196 I/O150 7B1 (io), 197 I/O151 7B0 (io), 200 I/O152 7A2 (io), 201 I/O153 7A3 (io), 202 I/O154 7A4 (io), 203 I/O155 7A7 (io), 204 I/O156 7A8 (io), 205 I/O157 7A11 (io), 206 I/O158 7A12 (io), 207 I/O159 7A13 (io)
part B pins: 1 TDI (in), 10 VCC (power), 11 GND (power), 20 GND (power), 25 I0/CLK0 (in), 26 VCC (power), 27 GND (power), 28 I1/CLK1 (in), 33 GND (power), 42 GND (power), 43 VCC (power), 52 TCK (in), 53 GND (power), 62 GND (power), 63 VCC (power), 72 GND (power), 77 VCC (power), 78 GND (power), 79 GND (power), 80 VCC (power), 85 GND (power), 94 VCC (power), 95 GND (power), 104 GND (power), 105 TMS (in), 114 VCC (power), 115 GND (power), 124 GND (power), 129 I2/CLK2 (in), 130 VCC (power), 131 GND (power), 132 I3/CLK3 (in), 137 GND (power), 146 GND (power), 147 VCC (power), 156 TDO (out), 157 GND (power), 166 GND (power), 167 VCC (power), 176 GND (power), 181 VCC (power), 182 GND (power), 183 GND (power), 184 VCC (power), 189 GND (power), 198 VCC (power), 199 GND (power), 208 GND (power)

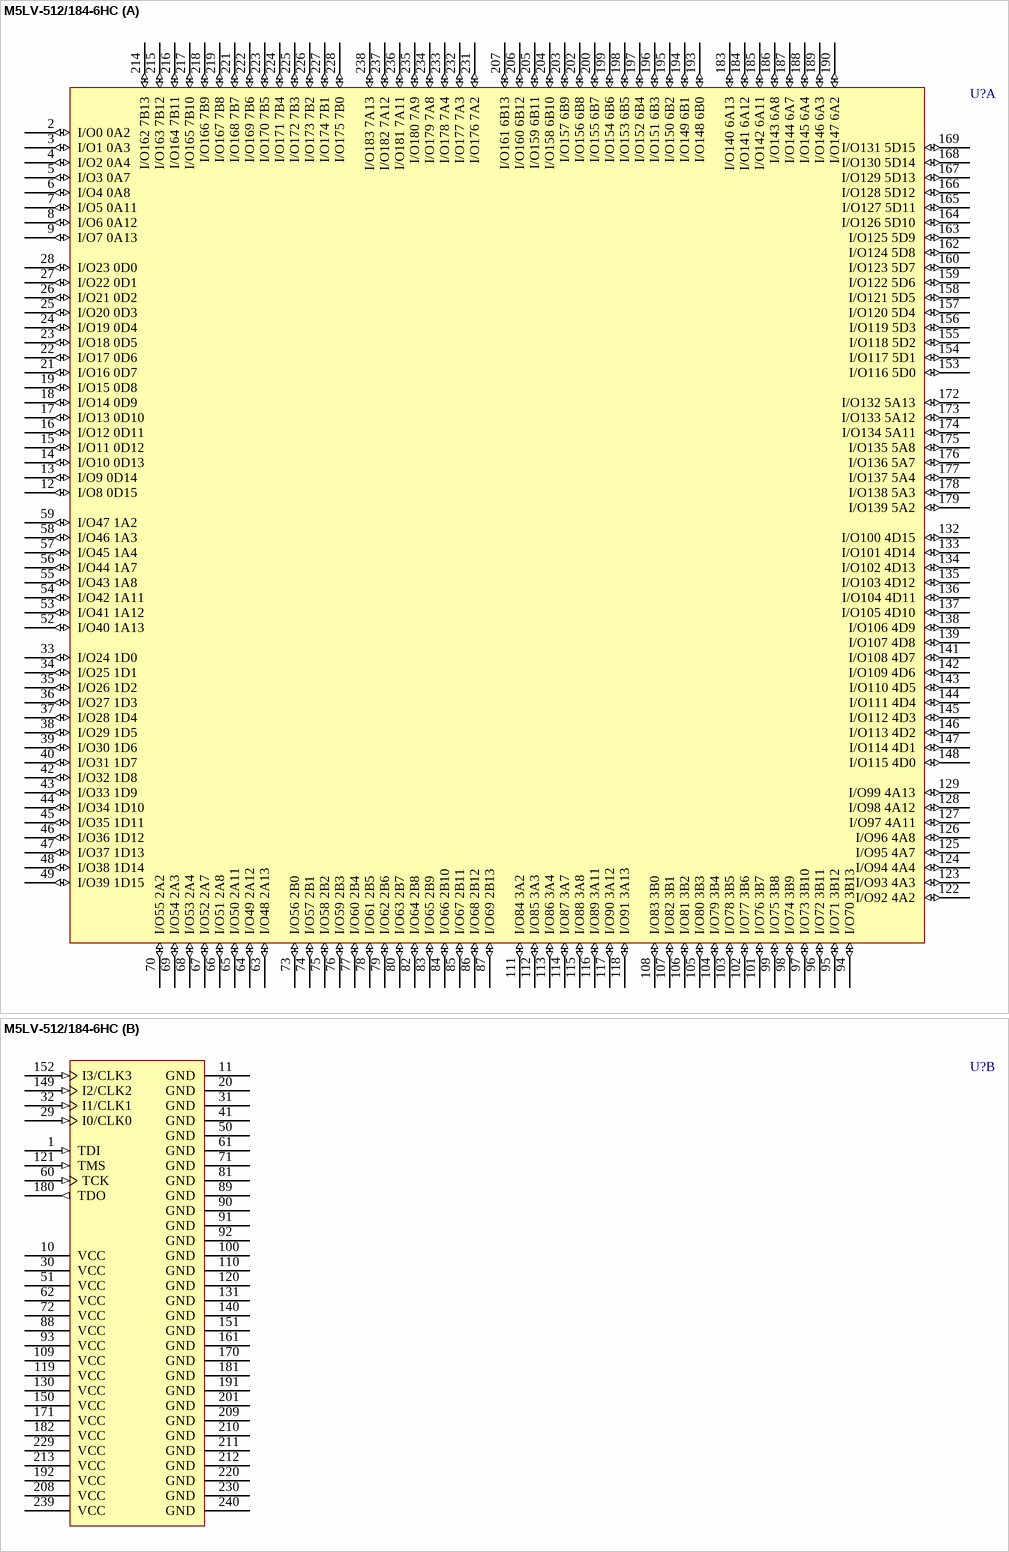
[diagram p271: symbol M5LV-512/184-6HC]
